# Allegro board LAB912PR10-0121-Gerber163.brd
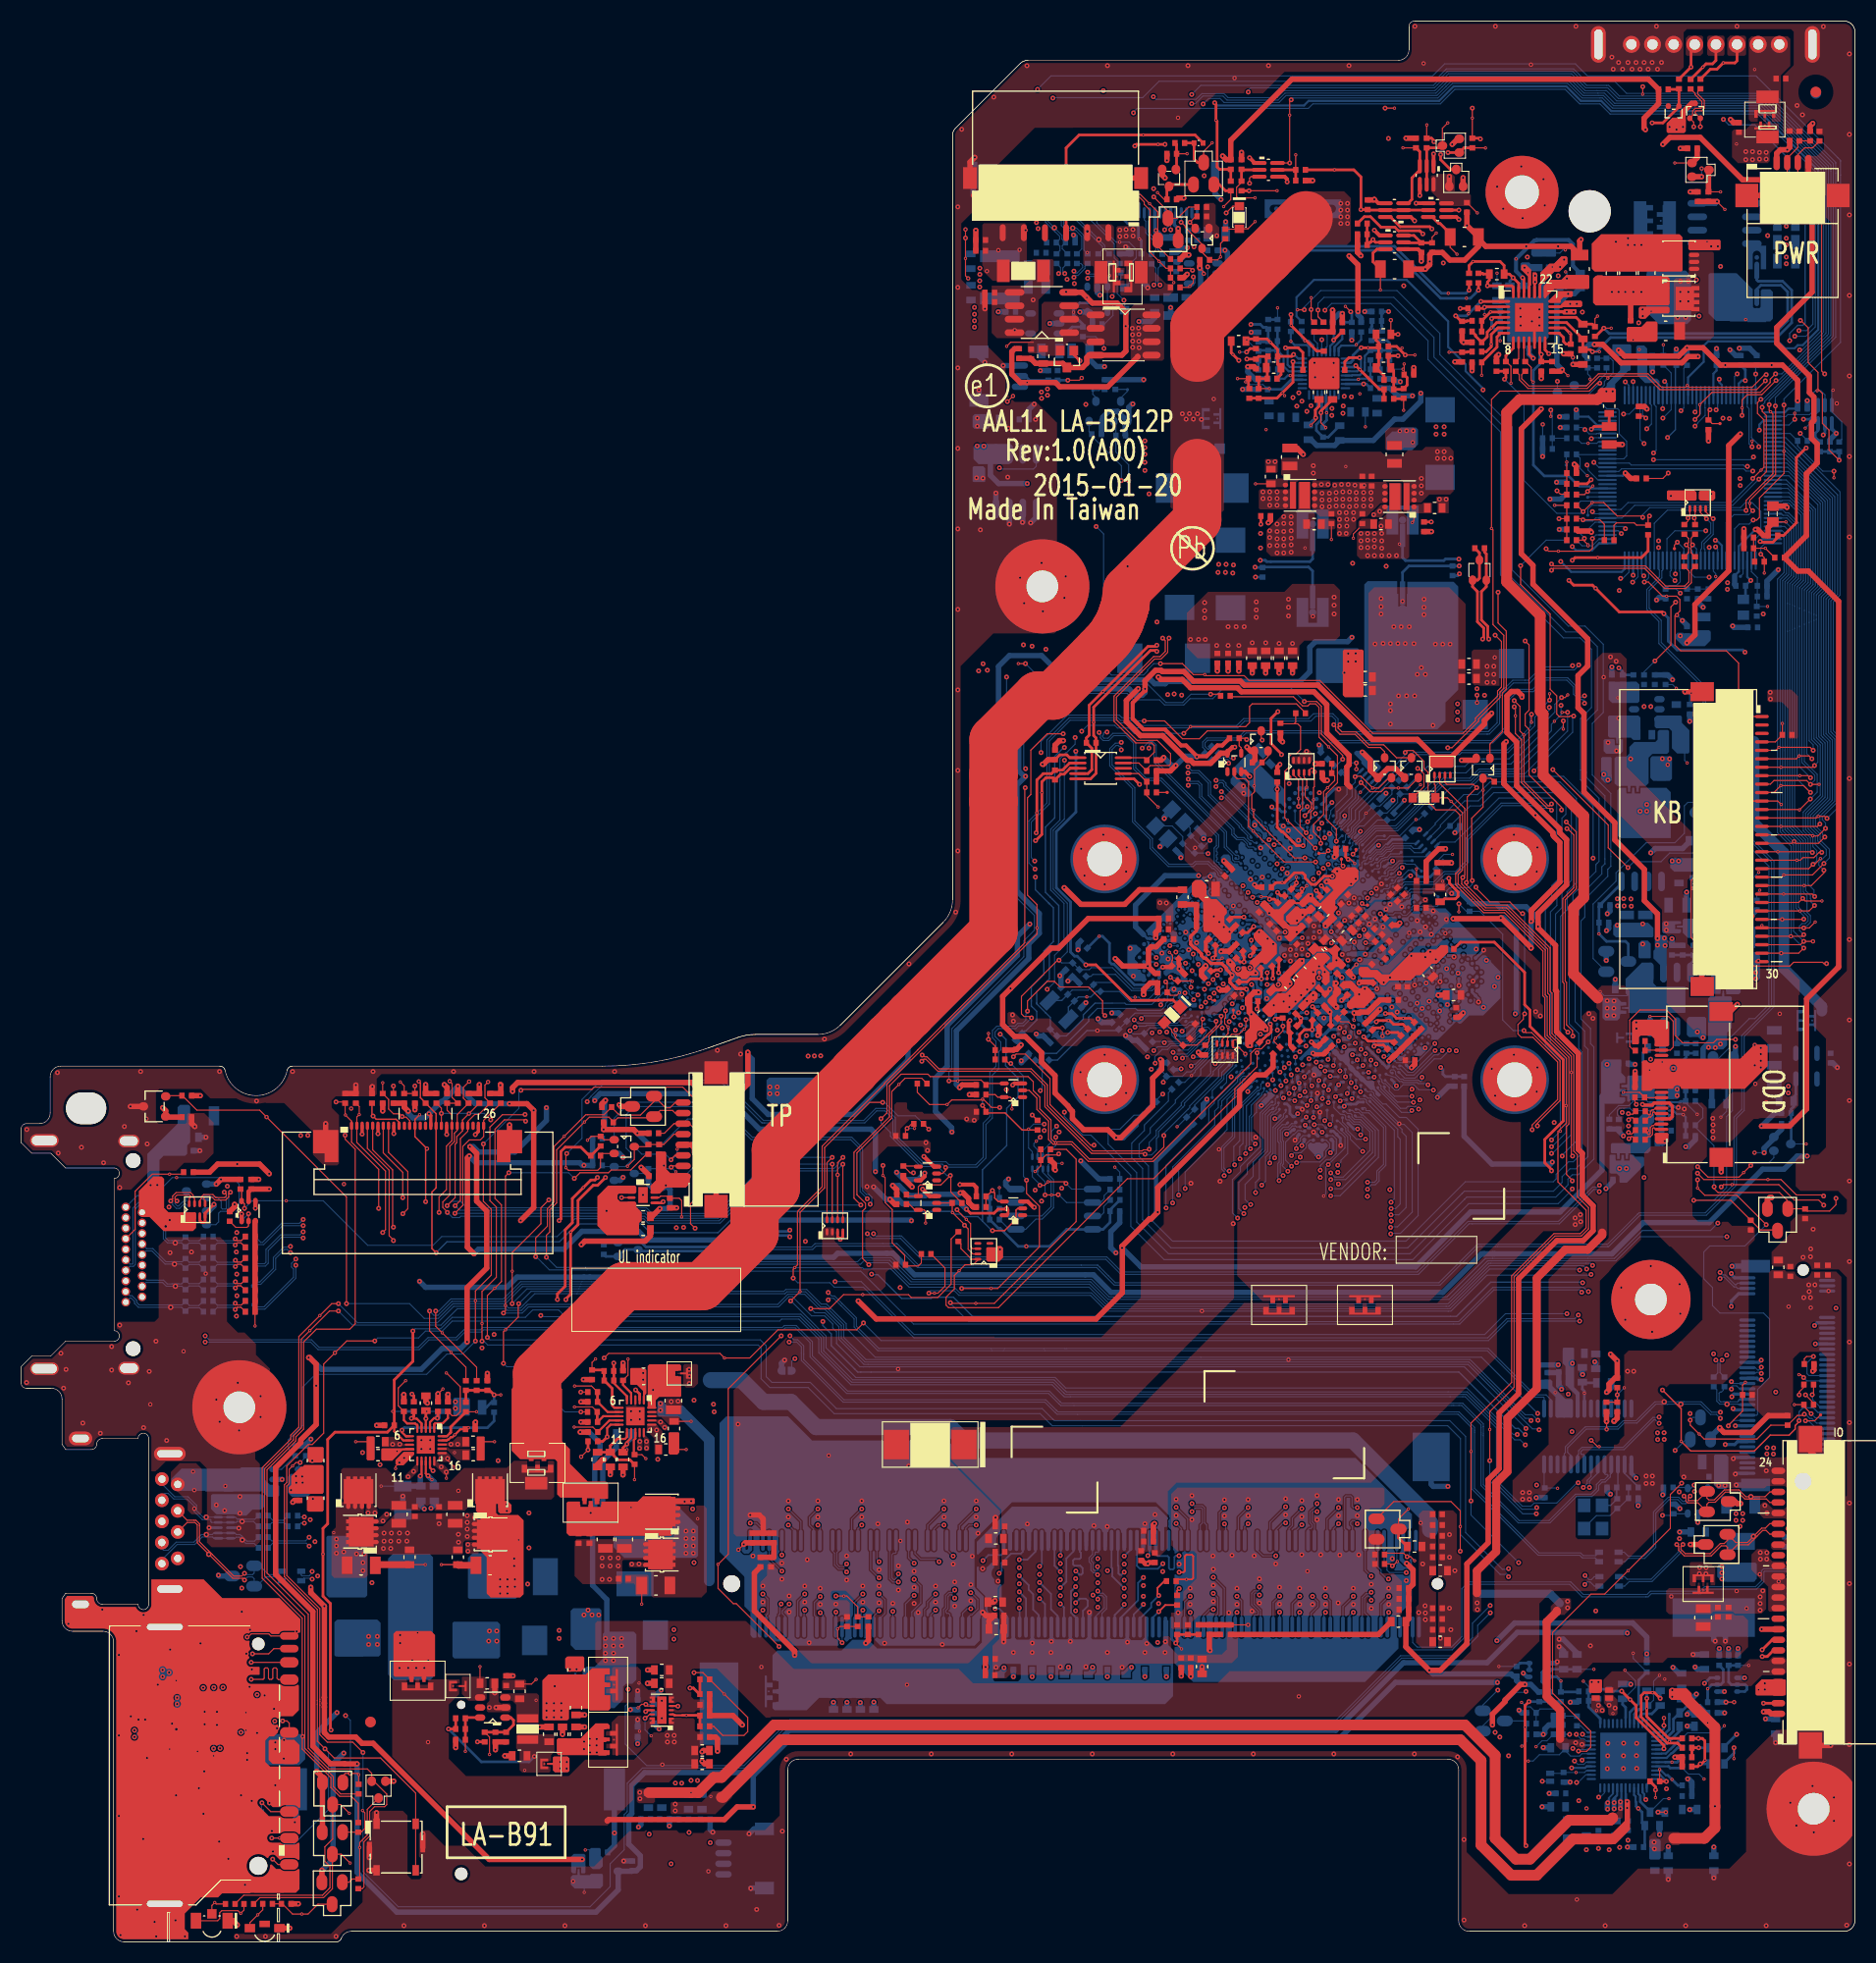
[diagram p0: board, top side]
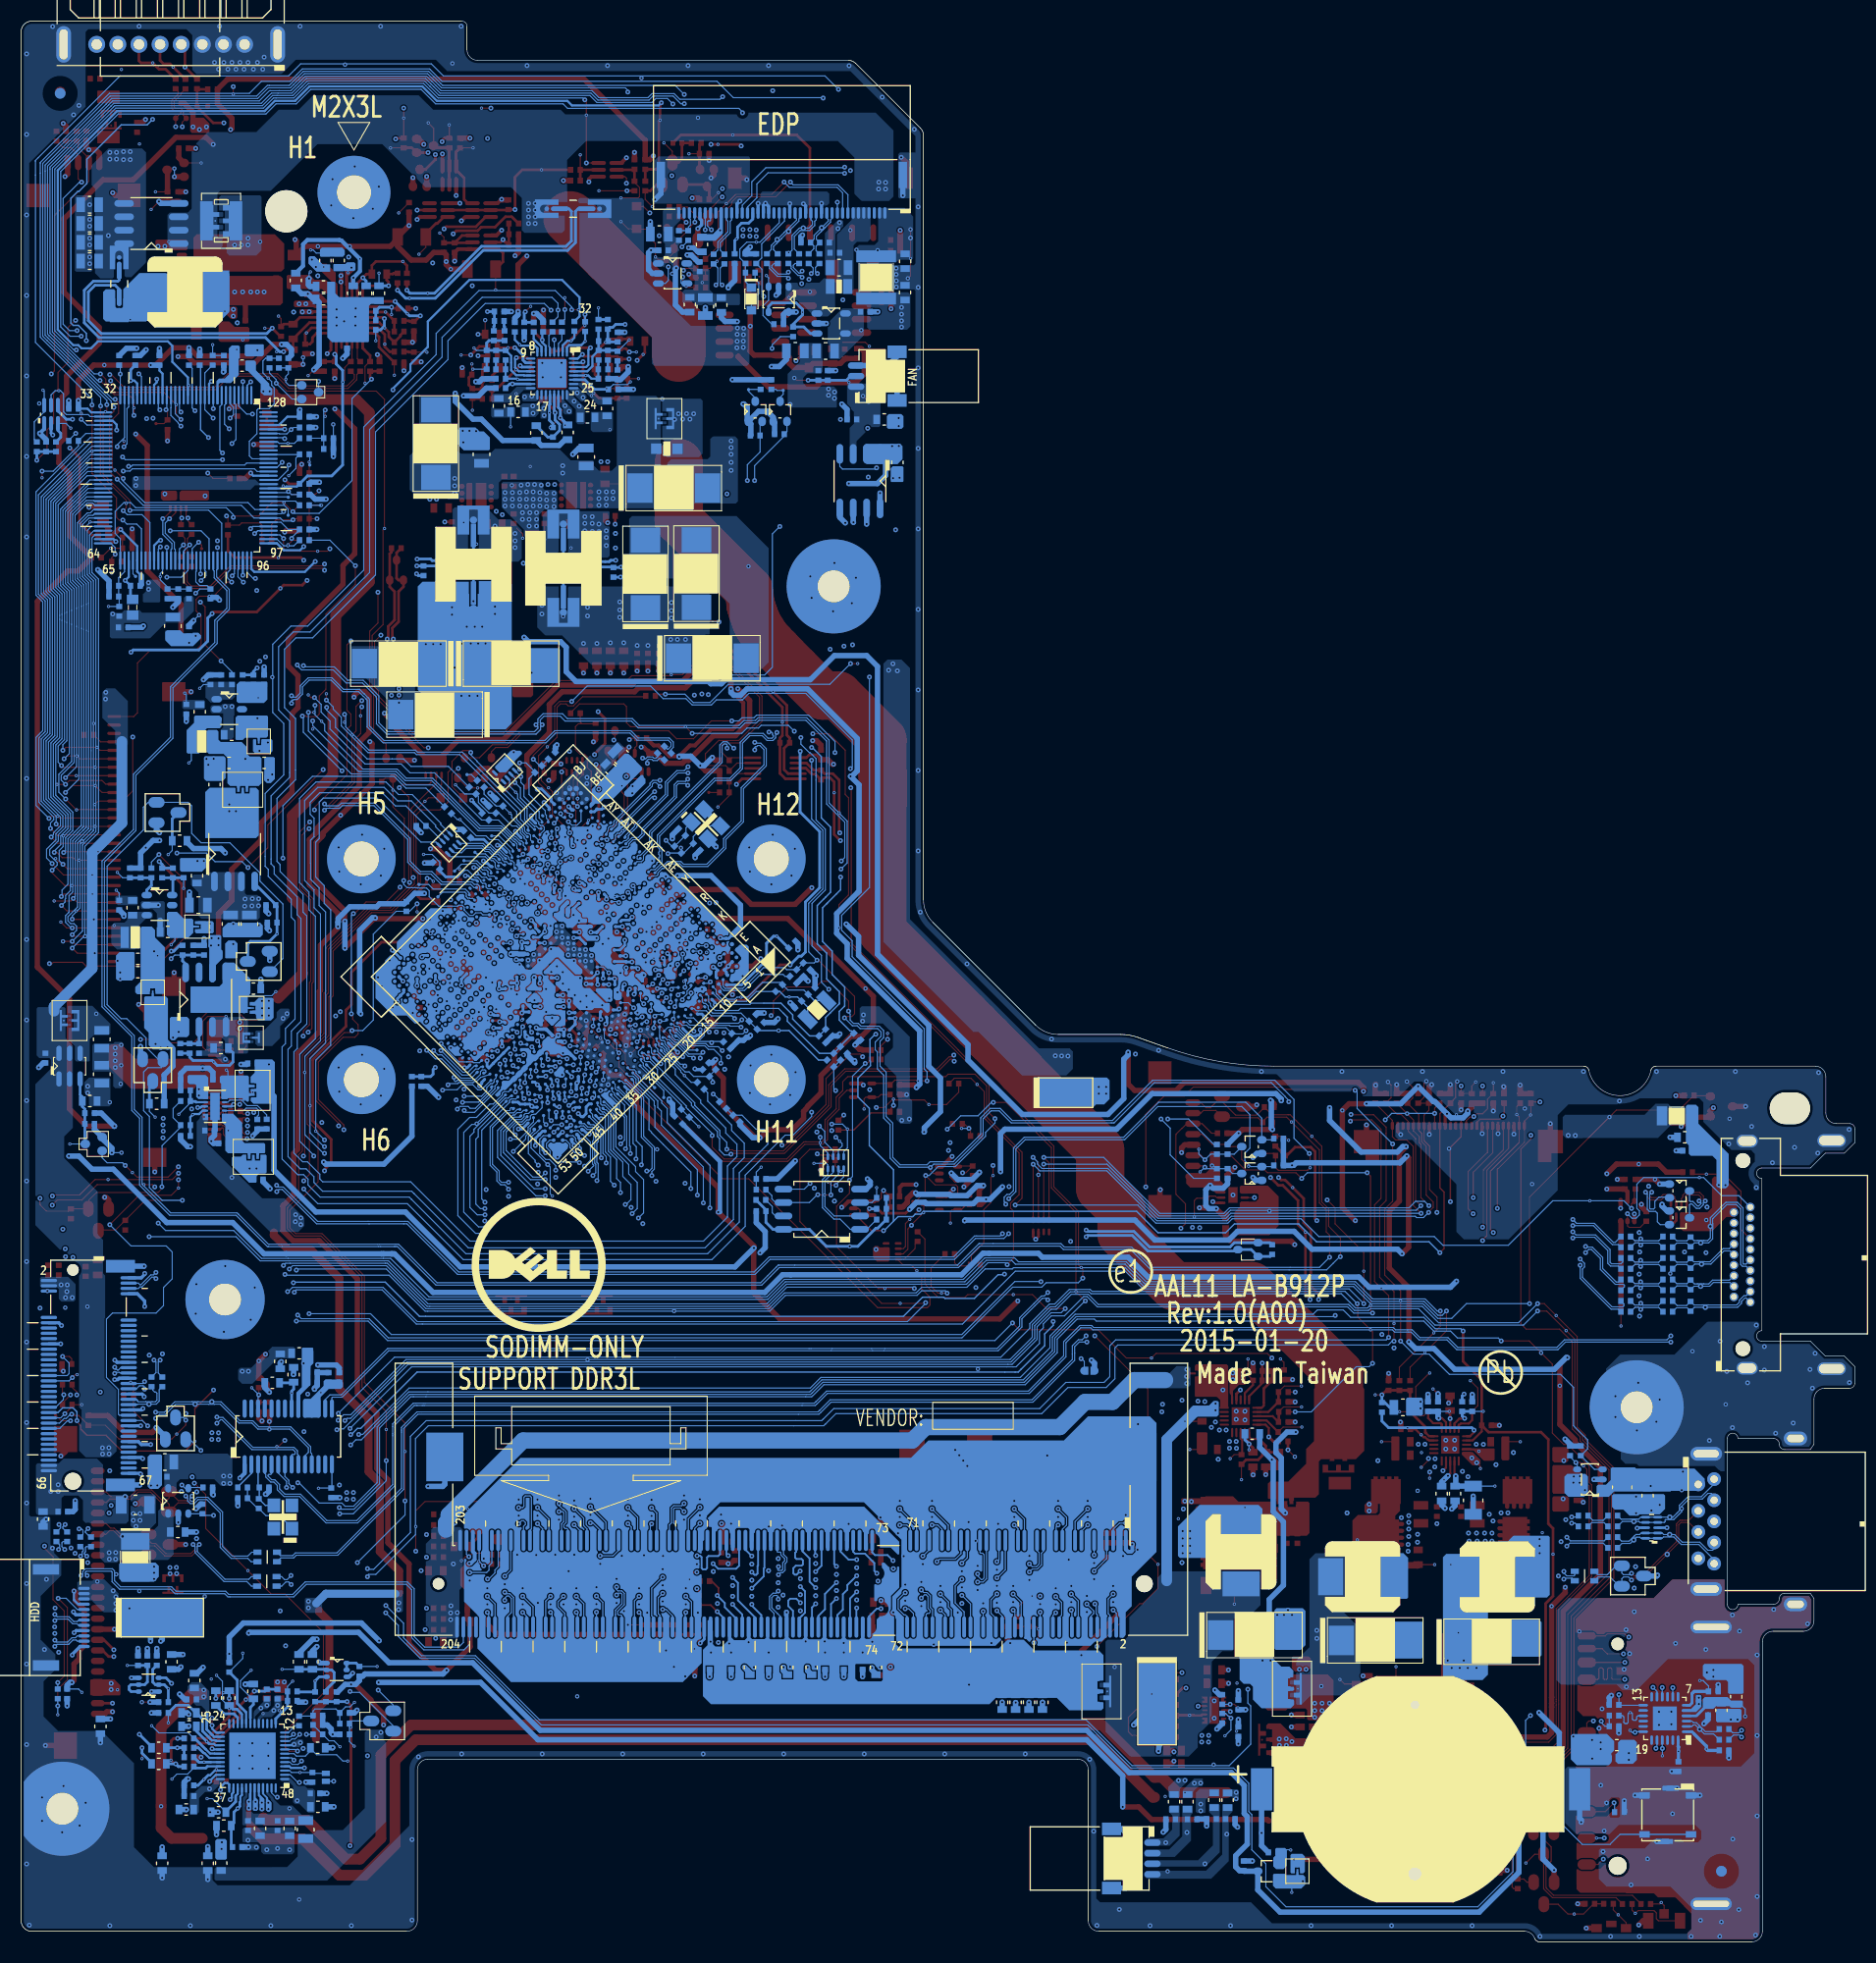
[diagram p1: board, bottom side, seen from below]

Outline 173.55 x 181.8 mm; copper layers: TOP, VCC, IN1, IN2, GND, BOTTOM. Coordinates in mm from the lower left corner of the outline.
Outline path: 0.5,52.4 arc(0.15,52.55) 0,52.9 0,54.45 1,55.45 2.8,55.45 4.2,56.85 8.8,56.85 arc(9.3,57.35) 8.8,57.85 8.8,72.25 arc(9.3,72.75) 8.8,73.25 4.2,73.25 2.8,74.65 1,74.65 0,75.65 0,76.95 arc(0.15,77.3) 0.5,77.45 1.75,77.45 arc(2.46,77.74) 2.75,78.45 2.75,81.89 arc(3.04,82.6) 3.75,82.89 18.81,82.89 ; 0.5,52.4 2.87,52.4 ; 0.5,52.4 2.87,52.4 ; 2.87,52.4 arc(3.58,52.11) 3.87,51.4 3.87,47.1 4.22,46.6 6.65,46.6 arc(7,46.75) 7.15,47.1 arc(7.31,47.49) 7.7,47.65 11.07,47.65 arc(11.57,48.15) 12.07,47.65 12.07,31.95 arc(11.57,31.45) 11.07,31.95 7.7,31.95 arc(7.31,32.11) 7.15,32.5 arc(7,32.85) 6.65,33 4.22,33 3.87,32.5 3.87,30.4 arc(4.16,29.69) 4.87,29.4 ; 18.81,82.89 arc(19.13,82.78) 19.3,82.49 ; 18.81,82.89 arc(19.13,82.78) 19.3,82.49 ; 4.87,29.4 7.75,29.4 ; 4.87,29.4 7.75,29.4 ; 7.75,29.4 arc(8.46,29.11) 8.75,28.4 8.75,1 arc(9.04,0.29) 9.75,0 ; 9.75,0 29.84,0 ; 9.75,0 29.84,0 ; 29.84,0 arc(30.12,0.09) 30.31,0.33 ; 29.84,0 arc(30.12,0.09) 30.31,0.33 ; 19.3,82.49 arc(22.24,80.1) 25.18,82.49 ; 25.18,82.49 arc(25.35,82.78) 25.67,82.89 ; 25.18,82.49 arc(25.35,82.78) 25.67,82.89 ; 25.67,82.89 55.01,82.89 arc(60.08,83.32) 65,84.6 ; 30.31,0.33 arc(30.67,0.82) 31.25,1 ; 31.25,1 71.55,1 ; 31.25,1 71.55,1 ; 71.55,1 arc(72.26,1.29) 72.55,2 ; 65,84.6 67.84,85.61 ; 65,84.6 67.84,85.61 ; 67.84,85.61 arc(68.66,85.82) 69.51,85.89 ; 67.84,85.61 arc(68.66,85.82) 69.51,85.89 ; 69.51,85.89 75.41,85.89 ; 69.51,85.89 75.41,85.89 ; 75.41,85.89 arc(76.56,86.12) 77.53,86.77 ; 72.55,16.29 72.55,2 ; 72.55,16.29 arc(72.84,17) 73.55,17.29 135.05,17.29 arc(135.76,17) 136.05,16.29 136.05,2 arc(136.34,1.29) 137.05,1 ; 72.55,16.29 72.55,2 ; 77.53,86.77 87.27,96.51 ; 77.53,86.77 87.27,96.51 ; 87.27,96.51 arc(87.92,97.48) 88.15,98.63 ; 88.15,170.98 88.15,98.63 ; 88.15,170.98 arc(88.23,171.36) 88.44,171.68 ; 88.15,170.98 arc(88.23,171.36) 88.44,171.68 ; 88.15,170.98 88.15,98.63 ; 88.44,171.68 94.56,177.8 ; 88.44,171.68 94.56,177.8 ; 94.56,177.8 arc(94.88,178.01) 95.26,178.09 ; 94.56,177.8 arc(94.88,178.01) 95.26,178.09 ; 95.26,178.09 130.35,178.09 arc(131.06,178.38) 131.35,179.09 ; 131.35,181.3 131.35,179.09 ; 131.35,181.3 arc(131.5,181.65) 131.85,181.8 ; 131.35,181.3 131.35,179.09 ; 131.85,181.8 172.55,181.8 ; 131.85,181.8 172.55,181.8 ; 172.55,181.8 arc(173.26,181.51) 173.55,180.8 ; 172.55,181.8 arc(173.26,181.51) 173.55,180.8 ; 137.05,1 172.55,1 ; 137.05,1 172.55,1 ; 172.55,1 arc(173.26,1.29) 173.55,2 ; 172.55,1 arc(173.26,1.29) 173.55,2 ; 173.55,180.8 173.55,2 ; 173.55,180.8 173.55,2

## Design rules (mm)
net group 20/15: nets USB20_JUSB2_N1_R USB20_JUSB2_P1_R
net group CSI: nets CSIN CSIP
net group DDI-COMP: nets DDI0_RCOMPN DDI0_RCOMPP
net group DIFFPAIR4: nets EC_SMB_CK2_EC EC_SMB_DA2_EC
net group DIFFPAIR7: nets MIC_CLK MIC_DATA
net group DIFFPAIR9: nets THERMAL_SMB_CK2 THERMAL_SMB_DA2
net group DIFFPAIR10: nets VCORE_GSNS VCORE_VSNS
net group PCIE-COMP: nets PCIE_RCOMPN PCIE_RCOMPP
net group REMOTE1: nets REMOTE1+ REMOTE1-
net group REMOTE2: nets REMOTE2+ REMOTE2-
net group SATA-RCOMP: nets SATA_RCOMPN SATA_RCOMPP
net group VSUM: nets VSUM+ VSUM-
net group VSUMG: nets VSUMG+ VSUMG-
net group 10: nets AUD_HP_OUT_L_CN AUD_HP_OUT_R_CN HPOUT-L HPOUT-R LINE-IN-L LINE-IN-R N17354752 N100764996 N100765116 N100768540
net group 15: nets EC_RSMRST# KB_RST# MIC_CLK_C PLT_RST# PMC_PLTRST# PMC_SUSCLK SOC_KBRST#
net group 20: nets DDR_RCOMP0 DDR_RCOMP1 DDR_RCOMP2 GPIO_RCOMP HSIC_RCOMP HUB_XIN HUB_XOUT ICLK_USB_TERMN ICLK_USB_TERMP ILB_RTC_X1 ILB_RTC_X2 LPC_RCOMP USB3_REXT0 USB_RCOMP VGFX_VSNS
net group CLK: nets DDR_TERMN0 DDR_TERMN1 ICLK_ICOMP ICLK_RCOMP XTAL_25M_IN XTAL_25M_OUT
net group DDR-CTL: nets DDR_A_CKE0 DDR_A_CKE2 DDR_A_CS0# DDR_A_CS2# DDR_A_ODT0 DDR_A_ODT2 M_ODT0 M_ODT1
net group DDRA-ADD: nets DDR_A_BS0 DDR_A_BS1 DDR_A_BS2 DDR_A_CAS# DDR_A_MA0 DDR_A_MA1 DDR_A_MA2 DDR_A_MA3 DDR_A_MA4 DDR_A_MA5 DDR_A_MA6 DDR_A_MA7 DDR_A_MA8 DDR_A_MA9 DDR_A_MA10 DDR_A_MA11 DDR_A_MA12 DDR_A_MA13 DDR_A_MA14 DDR_A_MA15 DDR_A_RAS# DDR_A_WE#
net group DDRA-D0: nets DDR_A_D0 DDR_A_D1 DDR_A_D2 DDR_A_D3 DDR_A_D4 DDR_A_D5 DDR_A_D6 DDR_A_D7 DDR_A_DM0 DDR_A_DQS0 DDR_A_DQS#0
net group DDRA-D1: nets DDR_A_D8 DDR_A_D9 DDR_A_D10 DDR_A_D11 DDR_A_D12 DDR_A_D13 DDR_A_D14 DDR_A_D15 DDR_A_DM1 DDR_A_DQS1 DDR_A_DQS#1
net group DDRA-D2: nets DDR_A_D16 DDR_A_D17 DDR_A_D18 DDR_A_D19 DDR_A_D20 DDR_A_D21 DDR_A_D22 DDR_A_D23 DDR_A_DM2 DDR_A_DQS2 DDR_A_DQS#2
net group DDRA-D3: nets DDR_A_D24 DDR_A_D25 DDR_A_D26 DDR_A_D27 DDR_A_D28 DDR_A_D29 DDR_A_D30 DDR_A_D31 DDR_A_DM3 DDR_A_DQS3 DDR_A_DQS#3
net group DDRA-D4: nets DDR_A_D32 DDR_A_D33 DDR_A_D34 DDR_A_D35 DDR_A_D36 DDR_A_D37 DDR_A_D38 DDR_A_D39 DDR_A_DM4 DDR_A_DQS4 DDR_A_DQS#4
net group DDRA-D5: nets DDR_A_D40 DDR_A_D41 DDR_A_D42 DDR_A_D43 DDR_A_D44 DDR_A_D45 DDR_A_D46 DDR_A_D47 DDR_A_DM5 DDR_A_DQS5 DDR_A_DQS#5
net group DDRA-D6: nets DDR_A_D48 DDR_A_D49 DDR_A_D50 DDR_A_D51 DDR_A_D52 DDR_A_D53 DDR_A_D54 DDR_A_D55 DDR_A_DM6 DDR_A_DQS6 DDR_A_DQS#6
net group DDRA-D7: nets DDR_A_D56 DDR_A_D57 DDR_A_D58 DDR_A_D59 DDR_A_D60 DDR_A_D61 DDR_A_D62 DDR_A_D63 DDR_A_DM7 DDR_A_DQS7 DDR_A_DQS#7
net group DDRCLK: nets DDR_A_CLK0 DDR_A_CLK0# DDR_A_CLK2 DDR_A_CLK2#
net group EDP: nets CPU_EDP_AUX#_C CPU_EDP_AUX_C CPU_EDP_N0_C CPU_EDP_N1_C CPU_EDP_P0_C CPU_EDP_P1_C EDP_CPU_AUX EDP_CPU_AUX# EDP_CPU_LANE_N0 EDP_CPU_LANE_N1 EDP_CPU_LANE_P0 EDP_CPU_LANE_P1
net group HDA: nets HDA_BIT_CLK HDA_BITCLK_AUDIO HDA_RCOMP HDA_RST# HDA_RST_AUDIO# HDA_SDIN0 HDA_SDOUT HDA_SDOUT_AUDIO HDA_SYNC HDA_SYNC_AUDIO
net group HDMI: nets HDMI_CLK+ HDMI_CLK- HDMI_TX0+ HDMI_TX0- HDMI_TX1+ HDMI_TX1- HDMI_TX2+ HDMI_TX2- TMDS_L_TX0N TMDS_L_TX0P TMDS_L_TX1N TMDS_L_TX1P TMDS_L_TX2N TMDS_L_TX2P TMDS_L_TXCN TMDS_L_TXCP TMDS_TX0N TMDS_TX0P TMDS_TX1N TMDS_TX1P TMDS_TX2N TMDS_TX2P TMDS_TXCN TMDS_TXCP
net group I2C: nets I2C1_SCL I2C1_SDA I2C2_SCL_TP I2C2_SCL_TP_R I2C2_SDA_TP I2C2_SDA_TP_R I2C5_SCL_PNL I2C5_SCL_PNL_R I2C5_SDA_PNL I2C5_SDA_PNL_R
net group KB: nets KSI0 KSI1 KSI2 KSI3 KSI4 KSI5 KSI6 KSI7 KSO0 KSO1 KSO2 KSO3 KSO4 KSO5 KSO6 KSO7 KSO8 KSO9 KSO10 KSO11 KSO12 KSO13 KSO14 KSO15 KSO16
net group LPC: nets LPC_AD0 LPC_AD1 LPC_AD2 LPC_AD3 LPC_CLK_0 LPC_CLK_1 LPC_CLK_EC LPC_CLKRUN# LPC_FRAME# SOC_SERIRQ
net group PCIE: nets CLK_PCIE_WLAN CLK_PCIE_WLAN# CLK_PCIE_WLAN#_R CLK_PCIE_WLAN_R PCIE_PRX_DTX_N1 PCIE_PRX_DTX_P1 PCIE_PTX_C_DRX_N1 PCIE_PTX_C_DRX_P1 PCIE_PTX_DRX_N1 PCIE_PTX_DRX_P1
net group RTC: nets ILB_RTC_EXTPAD RTC_RST# RTC_TEST#
net group SATA: nets SATA_PRX_DTX_N0 SATA_PRX_DTX_N0_C SATA_PRX_DTX_N1 SATA_PRX_DTX_N1_C SATA_PRX_DTX_P0 SATA_PRX_DTX_P0_C SATA_PRX_DTX_P1 SATA_PRX_DTX_P1_C SATA_PTX_DRX_N0 SATA_PTX_DRX_N0_C SATA_PTX_DRX_N1 SATA_PTX_DRX_N1_C SATA_PTX_DRX_P0 SATA_PTX_DRX_P0_C SATA_PTX_DRX_P1 SATA_PTX_DRX_P1_C
net group SD: nets MS_CLK_SD_WP MS_D1_SD_D3 MS_D2_SD_CLK MS_D2_SD_CLK_R SD_CD# SD_CMD SD_D0 SD_D1 SD_D2
net group SMBUS: nets CPU_DPB_CTRLCLK_R CPU_DPB_CTRLDAT_R DBG_UART_RXD DBG_UART_TXD EC_RX EC_SMB_CK1 EC_SMB_CK2 EC_SMB_DA1 EC_SMB_DA2 EC_TX HDMI_DDCCLK HDMI_DDCDATA PCU_SMB_CLK PCU_SMB_DATA TP_CLK TP_DATA
net group SPI: nets SOC_SPI_CLK SOC_SPI_CS0# SOC_SPI_MISO SOC_SPI_MOSI SPI_CLK SPI_CS0# SPI_HOLD# SPI_MISO SPI_MOSI SPI_WP#
net group SVID: nets VR_SVID_ALERT# VR_SVID_ALERT#_SOC VR_SVID_CLK VR_SVID_CLK_R VR_SVID_DATA VR_SVID_DATA_R VR_SVID_DATA_SOC
net group USB20: nets USB20_CAM_N2_R USB20_CAM_P2_R USB20_CPU_N3 USB20_CPU_P3 USB20_CR_N3_R USB20_CR_P3_R USB20_HUB_N1 USB20_HUB_N2 USB20_HUB_N3 USB20_HUB_N4 USB20_HUB_P1 USB20_HUB_P2 USB20_HUB_P3 USB20_HUB_P4 USB20_JUSB1_N0_R USB20_JUSB1_P0_R USB20_JUSB3_N3_R USB20_JUSB3_P3_R USB20_N0 USB20_N1 USB20_N2 USB20_P0 USB20_P1 USB20_P2
net group USB30: nets PCH_USB3_RX0_N PCH_USB3_RX0_P PCH_USB3_TX0_N PCH_USB3_TX0_N_C PCH_USB3_TX0_P PCH_USB3_TX0_P_C USB3RN2_JUSB1_R USB3RP2_JUSB1_R USB3TN2_JUSB1_R USB3TP2_JUSB1_R
nets with their own width: min track width 0.254; nets 1.0VS_GATE 3VS_ON 5VS_ON +1.0VS_R +1.5VSP +1.8VALW +1.8VS_OUT +3VALW_SOC +3VLP +3VS_SOC +BIOS_SPI +EC_VCCA +MIC2-VREFO +RTCBATT +V18R ACIN BATT_PRS BATT_TEMP CLK_SMB CS1 CS2 DAT_SMB EN_3V EN_5V EN_5V3V ENVDD_R ERP_LOT6 FAN_SPEED1 FB_3V FB_5V JACK_PLUG# JACK_SENSE# LINE1-L LINE1-R LINE1-VREFO-L LINE1-VREFO-R MIC1-L MIC_GND N17227663 N17227696 N17322935 N25654694 N25654700 N47008134 N48039107 N61580896 N61580898 N100764683 N100764685 N100764691 N100764720 N100764741 N100764791 N100764795 N100764809 N100764813 N100764860 N100764905 N100764954 N100765028 N100765040 N100765769 N100765781 NTC NTC_1 NTCG ODD_EN PS_ID PSID PSID-1 PSID-2 PSID-3 RING2 VGATE VR_HOT# VR_ON_R
nets with their own width: min track width 0.305; nets N40812716 RREF V18
nets with their own width: min track width 0.508; nets +1.0VALW +1.0VS +1.05VS +1.5VS +1.05VS_SOC +1.8VS +1.35V +1.35V_SOC +1.35VS +3V_HUB +3VALW +3VALWP +3VS +3VS_CAM +3VS_TP +5VALW +5VS +5VS_TOUCH +DDR_SOC_VREF +DIMM1_VREF_CA +DIMM1_VREF_DQ +FAN_POWER +INV_PWR_SRC +RTCVCC +SOC_VCC +SOC_VNN B+ BATT+ ECAGND GND GNDA HDMI_GND JHDD_P10 VIN VL
nets with their own width: min track width 0.635; nets SNB_3V SNB_5V
nets with their own width: min track width 0.762; nets +1.35VS_OUT DH_CHG DL_CHG LX_CHG
nets with their own width: min track width 1.016; nets +3VALW_EC +5V_HUB +5V_PVDD +VCC_3IN1 +VDISPLAY_VCC DH_1.35VP DL_1.35VP LG_3V LG_5V LGATE1 LGATEG LX_3V LX_5V PHASE1 PHASEG RING2_R SW_1.35VP UG_3V UG_5V UGATE1 UGATEG1
nets with their own width: min track width 1.524; nets +0.675VS +LCDVDD +LCDVDD_CONN
nets with their own width: min track width 2.032; nets +5V_USB_PWR1 +5V_USB_PWR2 +5VS_ODD +5VS_ODD_R1
nets with their own width: min track width 2.54; nets +3VS_WLAN_NGFF
nets with their own width: min track width 3.81; nets +3VS_OUT
nets with their own width: min track width 4.572; nets +5VS_OUT

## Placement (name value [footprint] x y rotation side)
C1  0.1U_0402_16V4Z  [C_0402]  15.22 78.06 0 top
C2  0.1U_0402_16V4Z  [C_0402]  167.38 170.49 90 top
C3  0.1U_0402_16V4Z  [C_0402]  170.2 171.37 270 top
C967  330P_0402_50V7K  [C_0402]  59.87 20.71 90 bottom
C976  330P_0402_50V7K  [C_0402]  59.87 23.4 270 bottom
C979  .1U_0402_16V7K  [C_0402]  65.16 23.45 180 top
C980  .1U_0402_16V7K  [C_0402]  64.24 21.42 0 top
C1034  1U_0402_6.3V6K  [C_0402]  109.06 94.91 180 top
C1035  1U_0402_6.3V6K  [C_0402]  107.55 90.76 90 top
C1036  1U_0402_6.3V6K  [C_0402]  116.66 92.78 315 top
C1037  1U_0402_6.3V6K  [C_0402]  115.91 91.51 225 top
C1038  0.47U_0402_6.3V6K  [C_0402]  120.73 86.69 225 top
C1039  0.01U_0402_16V7K  [C_0402]  114.98 94.4 315 top
C1040  1U_0402_6.3V6K  [C_0402]  122.71 87.93 45 top
C1041  1U_0402_6.3V6K  [C_0402]  124.53 91.68 135 top
C1042  1U_0402_6.3V6K  [C_0402]  125.66 91.79 135 top
C1043  1U_0402_6.3V6K  [C_0402]  120.08 98.28 315 top
C1044  1U_0402_6.3V6K  [C_0402]  117.3 94.69 225 top
C1045  1U_0402_6.3V6K  [C_0402]  114.81 89.55 135 top
C1046  1U_0402_6.3V6K  [C_0402]  127.21 97.09 135 top
C1047  1U_0402_6.3V6K  [C_0402]  126.57 96.46 135 top
C1048  1U_0402_6.3V6K  [C_0402]  108.59 96.86 180 top
C1049  1U_0402_6.3V6K  [C_0402]  108.59 95.84 180 top
C1050  1U_0402_6.3V6K  [C_0402]  124.28 98.88 315 top
C1051  1U_0402_6.3V6K  [C_0402]  128.83 94.06 45 top
C1052  1U_0402_6.3V6K  [C_0402]  121.46 98.42 315 top
C1053  1U_0402_6.3V6K  [C_0402]  129.09 93.05 45 top
C1054  1U_0402_6.3V6K  [C_0402]  123.42 85.45 315 top
C1055  1U_0402_6.3V6K  [C_0402]  122.78 84.82 315 top
C1056  22U_0805_6.3V6M  [C_0805]  151.95 95.5 90 bottom
C1057  22U_0805_6.3V6M  [C_0805]  153.73 95.5 90 bottom
C1058  1U_0402_6.3V6K  [C_0402]  127.84 92.53 225 top
C1059  22U_0805_6.3V6M  [C_0805]  157.63 98.13 180 bottom
C1060  1U_0402_6.3V6K  [C_0402]  111.96 91.25 45 top
C1061  1U_0402_6.3V6K  [C_0402]  126.17 90.28 225 top
C1062  1U_0402_6.3V6K  [C_0402]  117.73 93 315 top
C1063  .1U_0402_16V7K  [C_0402]  111.23 97.11 0 top
C1064  1U_0402_6.3V6K  [C_0402]  128.8 95.34 225 top
C1065  1U_0402_6.3V6K  [C_0402]  111.23 98.13 0 top
C1066  1U_0402_6.3V6K  [C_0402]  128.08 95.89 225 top
C1067  1U_0402_6.3V6K  [C_0402]  111.23 96.1 0 top
C1068  1U_0402_6.3V6K  [C_0402]  119.45 97.64 315 top
C1069  .1U_0402_16V7K  [C_0402]  124.91 99.77 315 top
C1070  0.01U_0402_16V7K  [C_0402]  128.59 91.4 225 top
C1071  1U_0402_6.3V6K  [C_0402]  130.26 98.49 135 top
C1072  1U_0402_6.3V6K  [C_0402]  130.89 99.12 135 top
C1073  1U_0402_6.3V6K  [C_0402]  132.06 97.87 0 top
C1074  1U_0402_6.3V6K  [C_0402]  114.99 93.12 135 top
C1075  1U_0402_6.3V6K  [C_0402]  134.04 101.23 90 top
C1076  .1U_0402_16V7K  [C_0402]  71.24 37.77 90 top
C1078  .1U_0402_16V7K  [C_0402]  112.45 30.01 270 top
C1117  .1U_0402_16V7K  [C_0402]  146.44 53.93 180 bottom
C1118  .1U_0402_16V7K  [C_0402]  146.44 52.92 180 bottom
C1119  10U_0603_10V6M  [C_0603]  147.76 52.98 90 bottom
C1120  10U_0603_6.3V6M  [C_0603]  149.03 55.65 270 bottom
C1121  0.01U_0402_16V7K  [C_0402]  151.06 51.09 270 top
C1122  0.01U_0402_16V7K  [C_0402]  144.46 53.88 270 bottom
C1123  330P_0402_50V7K  [C_0402]  151.2 76.93 90 bottom
C1124  .1U_0402_16V7K  [C_0402]  155.4 81.62 180 bottom
C1125  .1U_0402_16V7K  [C_0402]  158.45 80.6 180 bottom
C1126  .1U_0402_16V7K  [C_0402]  154.86 75.59 180 bottom
C1127  330P_0402_50V7K  [C_0402]  150.31 76.94 90 bottom
C1128  .1U_0402_16V7K  [C_0402]  158.45 76.28 180 bottom
C1129  4.7U_0603_6.3V6K  [C_0603]  155.25 110.26 270 bottom
C1130  4.7U_0603_6.3V6K  [C_0603]  156.9 101.62 270 bottom
C1131  .1U_0402_16V7K  [C_0402]  149.46 98.13 0 bottom
C1132  12P_0402_50V8J~N  [C_0402]  152.13 41.99 0 bottom
C1133  12P_0402_50V8J~N  [C_0402]  151.01 43.01 180 bottom
C1138  .1U_0402_16V7K  [C_0402]  58.35 19.44 90 bottom
C1139  .1U_0402_16V7K  [C_0402]  58.35 21.98 90 bottom
C1143  1U_0402_6.3V6K  [C_0402]  65.16 19.39 180 top
C1144  1U_0402_6.3V6K  [C_0402]  65.16 22.44 180 top
C1145  1U_0402_6.3V6K  [C_0402]  158.45 81.62 180 bottom
C1146  1U_0402_6.3V6K  [C_0402]  155.25 76.79 0 bottom
C1147  1U_0402_6.3V6K  [C_0402]  151.19 83.14 0 bottom
C1148  1U_0402_6.3V6K  [C_0402]  151.57 72.16 180 bottom
C2305  10U_0603_6.3V6M  [C_0603]  61.33 24.47 180 top
C2306  10U_0603_6.3V6M  [C_0603]  61.33 25.74 180 top
C2307  10U_0805_10V4Z  [C_0805]  52.51 24.89 90 top
C2308  10U_0603_6.3V6M  [C_0603]  52.51 22.88 270 top
C2316  10U_0603_6.3V6M  [C_0603]  63.75 18.12 0 top
C2318  10U_0603_6.3V6M  [C_0603]  63.75 16.85 0 top
C2323  10U_0603_6.3V6M  [C_0603]  52.51 18.94 90 top
C2324  10U_0603_6.3V6M  [C_0603]  51.24 18.94 90 top
C2498  0.1U_0402_10V6K  [C_0402]  97.85 111.89 90 top
C2500  2200P_0402_25V7K  [C_0402]  55.15 65.07 90 bottom
C2502  2200P_0402_25V7K  [C_0402]  97.85 110.9 270 top
C2504  2200P_0402_25V7K  [C_0402]  100.82 113.5 0 top
C2505  2200P_0402_25V7K  [C_0402]  137.59 131.91 0 top
CA1  10U_0603_6.3V6M  [C_0603]  147.25 25.8 90 bottom
CA2  10U_0603_6.3V6M  [C_0603]  145.98 25.8 90 bottom
CA21  22P_0402_50V8J  [C_0402]  145.93 20.53 180 bottom
CA22  22P_0402_50V8J  [C_0402]  145.98 16.04 270 bottom
CA23  2.2U_0603_6.3V6K  [C_0603]  158.36 20.4 180 bottom
CA24  1U_0402_6.3V6K  [C_0402]  154.16 15.2 0 top
CA25  1U_0402_6.3V6K  [C_0402]  158.12 14.82 180 bottom
CA29  1000P_0402_50V7K  [C_0402]  59.57 11.63 180 bottom
CA30  1000P_0402_50V7K  [C_0402]  60.43 11.63 0 bottom
CA31  1000P_0402_50V7K  [C_0402]  63.18 11.6 180 bottom
CA32  1000P_0402_50V7K  [C_0402]  64.29 11.6 0 bottom
CA51  0.1U_0402_16V7K  [C_0402]  156.95 22.94 0 bottom
CA53  4.7U_0603_6.3V6K  [C_0603]  148.14 11.45 270 bottom
CA54  0.1U_0402_16V7K  [C_0402]  152.08 11.46 270 bottom
CA55  4.7U_0603_6.3V6K  [C_0603]  150.93 11.45 270 bottom
CA56  0.1U_0402_16V7K  [C_0402]  149.28 11.46 270 bottom
CA57  4.7U_0603_6.3V6K  [C_0603]  146.17 12.78 180 bottom
CA58  0.1U_0402_16V7K  [C_0402]  146.18 14.05 180 bottom
CA59  4.7U_0603_6.3V6K  [C_0603]  157.22 12.53 0 bottom
CA60  0.1U_0402_16V7K  [C_0402]  157.21 13.8 0 bottom
CA61  10U_0603_6.3V6M  [C_0603]  153.66 11.01 0 bottom
CA62  10U_0603_6.3V6M  [C_0603]  158.36 21.67 180 bottom
CA63  10U_0603_6.3V6M  [C_0603]  155.57 12.28 180 bottom
CA64  10U_0603_6.3V6M  [C_0603]  144.77 18.37 0 bottom
CA65  0.1U_0402_16V7K  [C_0402]  147.25 20.45 90 bottom
CA67  4.7U_0603_6.3V6K  [C_0603]  155.12 22.37 90 bottom
CA68  4.7U_0603_6.3V6K  [C_0603]  153.85 22.37 90 bottom
CA69  100P_0402_50V8J  [C_0402]  145.93 21.42 180 bottom
CA71  4.7U_0603_6.3V6K  [C_0603]  157.16 24.02 90 bottom
CA74  10U_0603_6.3V6M  [C_0603]  151.57 23.01 90 bottom
CC1  .1U_0402_16V7K  [C_0402]  125.21 88.03 45 top
CC2  .1U_0402_16V7K  [C_0402]  127.89 86.31 135 top
CC5  0.1U_0402_10V7K  [C_0402]  113.31 112.51 135 bottom
CC6  0.1U_0402_10V7K  [C_0402]  112.68 111.87 135 bottom
CC7  22P_0402_50V8J  [C_0402]  135.24 105.62 0 bottom
CC8  10P_0402_50V8J  [C_0402]  109.05 82.56 225 bottom
CC9  10P_0402_25V8K  [C_0402]  110.69 104.71 45 bottom
CC10  10P_0402_25V8K  [C_0402]  109.94 103.96 225 bottom
CC11  .1U_0402_16V7K  [C_0402]  91.32 70.57 180 top
CC12  .1U_0402_16V7K  [C_0402]  123.65 111.95 135 bottom
CC13  .1U_0402_16V7K  [C_0402]  112.07 84.87 270 top
CC14  .1U_0402_16V7K  [C_0402]  98.04 85.75 225 bottom
CC15  .1U_0402_16V7K  [C_0402]  100.79 91.39 225 bottom
CC16  .1U_0402_16V7K  [C_0402]  100.16 92.02 225 bottom
CC17  15P_0402_50V8J  [C_0402]  99.06 89.68 135 bottom
CC18  15P_0402_50V8J  [C_0402]  99.68 89.05 315 bottom
CC19  .1U_0402_16V7K  [C_0402]  124.59 87.4 225 top
CC20  1U_0402_6.3V6K  [C_0402]  94.09 85.36 45 bottom
CC21  .1U_0402_16V7K  [C_0402]  103.06 69.17 0 bottom
CC22  1U_0402_6.3V6K  [C_0402]  104.65 87.14 135 bottom
CC23  .1U_0402_16V7K  [C_0402]  57.84 6.74 90 bottom
CC24  10P_0402_50V8J  [C_0402]  103.06 72.21 0 bottom
CC25  10P_0402_50V8J  [C_0402]  128.62 106.84 45 bottom
CC26  10P_0402_50V8J  [C_0402]  127.96 107.51 45 bottom
CC27  1U_0402_6.3V6K  [C_0402]  127.75 88.31 135 top
CC28  .1U_0402_16V7K  [C_0402]  128.38 88.95 135 top
CC29  2.2U_0402_6.3V6M  [C_0402]  131.91 83.44 180 top
CC30  2.2U_0402_6.3V6M  [C_0402]  130.31 91.32 270 top
CC31  2.2U_0402_6.3V6M  [C_0402]  135.82 87.51 90 top
CC32  2.2U_0402_6.3V6M  [C_0402]  131.2 91.32 270 top
CC33  10U_0603_6.3V6M  [C_0603]  136.26 89.62 180 top
CC34  10U_0603_6.3V6M  [C_0603]  133.6 91.33 135 top
CC35  10U_0603_6.3V6M  [C_0603]  117.25 110.51 45 bottom
CC36  22U_0805_6.3V6M  [C_0805]  116.12 111.54 45 bottom
CC38  22U_0805_6.3V6M  [C_0805]  113.05 99.65 180 top
CC39  1U_0402_6.3V6K  [C_0402]  121 85.26 225 top
CC40  1U_0402_6.3V6K  [C_0402]  119.04 92.95 135 top
CC41  1U_0402_6.3V6K  [C_0402]  122.2 87.23 315 top
CC42  1U_0402_6.3V6K  [C_0402]  124.53 89.9 45 top
CC43  1U_0402_6.3V6K  [C_0402]  113.92 100.88 45 top
CC44  1U_0402_6.3V6K  [C_0402]  124.09 89.05 135 top
CC45  1U_0402_6.3V6K  [C_0402]  118.18 96.33 45 top
CC46  1U_0402_6.3V6K  [C_0402]  117.16 97.47 45 top
CC47  1U_0402_6.3V6K  [C_0402]  118.81 95.69 45 top
CC49  .1U_0402_16V7K  [C_0402]  37.27 80.3 270 top
CC50  .1U_0402_16V7K  [C_0402]  30.66 79.38 90 top
CC51  .1U_0402_16V7K  [C_0402]  38.28 79.38 90 top
CC52  .1U_0402_16V7K  [C_0402]  31.68 79.38 90 top
CC53  .1U_0402_16V7K  [C_0402]  39.3 79.38 90 top
CC54  .1U_0402_16V7K  [C_0402]  33.2 79.38 90 top
CC56  .1U_0402_16V7K  [C_0402]  40.32 79.38 90 top
CC57  .1U_0402_16V7K  [C_0402]  34.22 80.3 270 top
CC59  .1U_0402_16V7K  [C_0402]  42.35 79.38 90 top
CC61  .1U_0402_16V7K  [C_0402]  43.36 79.38 90 top
CC63  .1U_0402_16V7K  [C_0402]  44.38 79.38 90 top
CC65  .1U_0402_16V7K  [C_0402]  45.4 79.38 90 top
CD1  2.2U_0402_6.3V6M  [C_0402]  69.21 37.77 90 top
CD2  0.1U_0402_10V7K  [C_0402]  70.23 37.77 90 top
CD3  0.1U_0402_10V7K  [C_0402]  78.16 29.85 90 top
CD4  0.1U_0402_10V7K  [C_0402]  92.17 25.24 180 top
CD5  0.1U_0402_10V7K  [C_0402]  106.24 38.91 0 top
CD6  0.1U_0402_10V7K  [C_0402]  97.47 26.7 270 bottom
CD7  0.1U_0402_10V7K  [C_0402]  92.18 26.78 180 top
CD8  0.1U_0402_10V7K  [C_0402]  93.1 39.33 180 top
CD9  0.1U_0402_10V7K  [C_0402]  93.91 26.7 270 bottom
CD10  0.1U_0402_10V7K  [C_0402]  108.39 26.7 270 bottom
CD11  0.1U_0402_10V7K  [C_0402]  93.01 30.88 180 top
CD12  10U_0603_6.3V6M  [C_0603]  92.89 32.15 180 top
CD13  10U_0603_6.3V6M  [C_0603]  93 29.61 180 top
CD14  10U_0603_6.3V6M  [C_0603]  111.77 26.77 270 top
CD15  330U_D2_2.5V_R6M  [C_D2]  89.24 47.07 180 top
CD16  10U_0603_6.3V6M  [C_0603]  92.64 26.69 270 bottom
CD17  10U_0603_6.3V6M  [C_0603]  101.02 26.69 270 bottom
CD18  10U_0603_6.3V6M  [C_0603]  98.74 26.69 270 bottom
CD19  10U_0603_6.3V6M  [C_0603]  92.96 38.18 180 top
CD20  10U_0603_6.3V6M  [C_0603]  104.58 26.69 270 bottom
CD21  2.2U_0402_6.3V6M  [C_0402]  110.42 29.09 90 top
CD22  0.1U_0402_10V7K  [C_0402]  109.4 29.09 90 top
CD24  1U_0402_6.3V6K  [C_0402]  133.58 37.42 0 top
CD25  1U_0402_6.3V6K  [C_0402]  133.58 36.41 0 top
CD26  1U_0402_6.3V6K  [C_0402]  133.58 31.58 0 top
CD27  1U_0402_6.3V6K  [C_0402]  133.58 38.44 0 top
CD28  10U_0603_6.3V6M  [C_0603]  133.6 28.41 0 top
CD29  10U_0603_6.3V6M  [C_0603]  133.6 35.14 0 top
CD30  2.2U_0402_6.3V6M  [C_0402]  131.32 33.49 180 top
CD31  0.1U_0402_10V7K  [C_0402]  131.32 31.45 180 top
CD32  330U_D2_2.5V_R6M  [C_D2]  130.38 120.99 180 bottom
CD33  2.2U_0402_6.3V6M  [C_0402]  102.8 26.7 270 bottom
CD34  2.2U_0402_6.3V6M  [C_0402]  106.24 37.89 0 top
CD35  2.2U_0402_6.3V6M  [C_0402]  106.36 26.7 270 bottom
CD36  2.2U_0402_6.3V6M  [C_0402]  107.3 36.83 270 top
CD37  2.2U_0402_6.3V6M  [C_0402]  93.1 35.9 180 top
CD38  10P_0402_25V8K  [C_0402]  93.1 36.91 180 top
CD39  10P_0402_25V8K  [C_0402]  109.8 26.87 270 top
CD40  10P_0402_25V8K  [C_0402]  110.7 26.87 270 top
CD41  10P_0402_25V8K  [C_0402]  106 37.02 270 top
CD42  10P_0402_25V8K  [C_0402]  95.69 26.7 270 bottom
CD43  2.2U_0402_6.3V6M  [C_0402]  133.58 30.56 0 top
CD44  10P_0402_25V8K  [C_0402]  133.58 39.45 0 top
CD45  2.2U_0402_6.3V6M  [C_0402]  133.58 40.47 0 top
CD46  10P_0402_25V8K  [C_0402]  133.58 29.55 0 top
CD47  0.1U_0402_10V7K  [C_0402]  131.32 32.47 180 top
CD62  22U_0603_6.3V6M  [C_0603]  131.06 30.31 180 top
CE1  0.1U_0402_10V7K  [C_0402]  168.13 145.12 0 bottom
CE2  0.1U_0402_10V7K  [C_0402]  164.34 124.42 180 bottom
CE5  1000P_0402_50V7K  [C_0402]  146.28 144.36 0 bottom
CE6  1000P_0402_50V7K  [C_0402]  160.46 150.15 270 bottom
CE7  0.1U_0402_10V7K  [C_0402]  163.2 128.35 180 bottom
CE8  0.1U_0402_10V7K  [C_0402]  164.32 128.35 0 bottom
CE9  100P_0402_50V8J  [C_0402]  165.33 133.12 0 top
CE10  0.1U_0402_10V7K  [C_0402]  159.7 128.05 270 bottom
CE12  0.1U_0402_10V7K  [C_0402]  154.36 150.15 270 bottom
CE16  4.7U_0805_10V4Z  [C_0805]  150.3 143.43 270 top
CE18  100P_0402_50V8J  [C_0402]  146.28 138.01 0 bottom
CE20  0.1U_0402_16V7K  [C_0402]  168.29 170.47 90 top
CE23  1000P_0402_50V7K  [C_0402]  94.47 144.1 0 bottom
CE24  2.2U_0603_6.3V6K  [C_0603]  92.58 144.1 180 bottom
CE25  2.2U_0603_6.3V6K  [C_0603]  90.61 140.74 270 bottom
CE26  0.1U_0402_10V7K  [C_0402]  153.8 138.51 180 top
CE27  0.1U_0402_10V7K  [C_0402]  153.09 144.41 90 top
CE28  0.1U_0402_10V7K  [C_0402]  147.2 143.34 180 bottom
CE29  220P_0402_50V8J  [C_0402]  162.74 149.23 90 bottom
CE31  0.1U_0402_10V7K  [C_0402]  99.52 92.66 225 bottom
CE32  0.01U_0402_16V7K  [C_0402]  97.21 147.81 90 bottom
CE34  0.1U_0402_10V7K  [C_0402]  144.91 141.31 180 bottom
CE35  220P_0402_50V8J  [C_0402]  159.7 144.05 270 top
CE36  0.047U_0402_16V4Z  [C_0402]  156.65 149.23 90 bottom
CE59  0.1U_0402_10V6K  [C_0402]  60.33 72.47 180 top
CE60  2200P_0402_25V7K  [C_0402]  61.4 70.39 270 top
CE61  1U_0402_6.3V6K  [C_0402]  157.66 124.49 270 bottom
CI1  100U_1206_6.3V M X5R  [C_1206]  22.03 44.34 270 bottom
CI2  0.1U_0402_16V7K  [C_0402]  18.34 42.96 270 bottom
CI3  0.1U_0402_10V7K  [C_0402]  25.25 39.33 0 bottom
CI4  0.1U_0402_10V7K  [C_0402]  25.25 40.34 0 bottom
CI6  4.7U_0805_10V4Z  [C_0805]  159.1 45.42 0 bottom
CI7  0.1U_0402_16V7K  [C_0402]  159.75 44.03 0 bottom
CI12  4.7U_0805_10V4Z  [C_0805]  27.87 44.7 90 top
CI13  0.1U_0402_16V7K  [C_0402]  26.96 46.02 90 bottom
CI14  0.1U_0402_16V7K  [C_0402]  26.35 42.71 270 top
CI15  0.1U_0402_16V7K  [C_0402]  25.94 46.02 90 bottom
CI17  0.1U_0402_16V7K  [C_0402]  156.39 40.52 90 bottom
CI18  47U_0805_6.3V4Z  [C_0805]  27.87 42.84 270 top
CI19  150U_B15G_6.3VM_R70M  [C_B15G]  162.74 37.91 270 bottom
CI26  0.1U_0402_16V7K  [C_0402]  156.34 43.01 180 bottom
CI40  10U_0603_6.3V6M  [C_0603]  19.61 42.95 270 bottom
CLIP1  -  [EMIST-SQ-26G_1P]  74.68 80.38 180 bottom
CLIP2  -  [EMIST_SQ-55G_1P]  66.05 22.55 270 bottom
CLIP3  -  [EMIST_SQ-55G_1P]  160.19 30.69 180 bottom
CLRP1  SHORT PADS  [SHORTPADS]  72.45 54.06 180 bottom
CM4  22U_0603_6.3V6M~D  [C_0603]  166.3 63.14 90 top
CM5  0.1U_0402_10V7K~D  [C_0402]  171 63.13 90 top
CM6  22U_0603_6.3V6M~D  [C_0603]  171.47 40.72 270 bottom
CM7  0.1U_0402_10V7K~D  [C_0402]  170.06 40.72 180 bottom
CM8  10P_0402_50V8J  [C_0402]  167.44 63 90 top
CM9  2.2U_0402_6.3V6M  [C_0402]  169.98 63.13 90 top
CR1  0.1U_0402_10V7K  [C_0402]  13.9 22.39 270 bottom
CR2  4.7U_0603_6.3V6K  [C_0603]  12.63 22.63 270 bottom
CR3  1U_0402_6.3V6K  [C_0402]  12.93 23.71 0 bottom
CR4  1U_0402_6.3V6K  [C_0402]  16.69 16.14 90 bottom
CR6  5P_0402_50V8C  [C_0402]  23.25 20.4 180 bottom
CR7  0.1U_0402_10V7K  [C_0402]  23.25 17.36 180 bottom
CR8  4.7U_0603_6.3V6K  [C_0603]  23.23 18.63 180 bottom
CR9  22P_0402_50V8J  [C_0402]  22.33 22.44 0 bottom
CR11  22P_0402_50V8J  [C_0402]  22.74 12.28 180 bottom
CS5  1000P_0402_50V7K  [C_0402]  160.58 31.66 270 top
CS6  0.1U_0402_25V6K  [C_0402]  161.6 31.66 270 top
CS7  10U_0805_10V6K  [C_0805]  159.19 31.54 270 top
CS8  0.01U_0402_16V7K  [C_0402]  153.7 75.93 180 top
CS9  0.01U_0402_16V7K  [C_0402]  153.7 76.83 180 top
CS10  1000P_0402_50V7K  [C_0402]  153.65 80.89 180 top
CS11  0.1U_0402_25V6K  [C_0402]  153.66 81.78 180 top
CS12  10U_0805_10V6K  [C_0805]  165.92 82.98 270 bottom
CS13  1U_0402_6.3V6K  [C_0402]  171.25 84.11 270 bottom
CS14  0.01U_0402_16V7K  [C_0402]  153.71 77.73 180 top
CS15  0.01U_0402_16V7K  [C_0402]  153.71 78.62 180 top
CS16  0.1U_0603_25V7K  [C_0603]  167.76 79.59 180 bottom
CS17  0.1U_0402_25V6K  [C_0402]  153.69 85.26 180 top
CS30  0.01U_0402_16V7K  [C_0402]  170.21 38.81 270 bottom
CS31  0.01U_0402_16V7K  [C_0402]  166.93 38.32 270 bottom
CS32  0.01U_0402_16V7K  [C_0402]  169.2 38.81 270 bottom
CS34  0.01U_0402_16V7K  [C_0402]  167.95 38.32 270 bottom
CX5  0.1U_0603_25V7K  [C_0603]  89.88 159.77 270 bottom
CX6  0.1U_0402_16V7K  [C_0402]  109.33 158.1 90 bottom
CX7  4.7U_0805_10V4Z  [C_0805]  99.42 150.59 0 bottom
CX8  10U_0805_10V6K  [C_0805]  95.29 158.47 0 bottom
CX9  0.1U_0402_10V7K  [C_0402]  94.11 154.29 180 bottom
CX10  0.1U_0603_25V7K  [C_0603]  89.9 155.41 90 bottom
CX11  0.1U_0402_10V7K  [C_0402]  96.08 159.88 0 bottom
CX12  0.1U_0402_10V7K  [C_0402]  21.22 64.73 0 bottom
CX13  0.1U_0402_10V7K  [C_0402]  21.22 63.71 0 bottom
CX14  0.1U_0402_10V7K  [C_0402]  21.22 66.76 0 bottom
CX15  0.1U_0402_10V7K  [C_0402]  21.22 65.74 0 bottom
CX16  0.1U_0402_10V7K  [C_0402]  21.22 62.69 0 bottom
CX17  0.1U_0402_10V7K  [C_0402]  21.22 61.68 0 bottom
CX18  0.1U_0402_10V7K  [C_0402]  21.22 60.66 0 bottom
CX19  0.1U_0402_10V7K  [C_0402]  21.22 59.65 0 bottom
CX21  0.1U_0402_16V7K  [C_0402]  15.38 74.89 0 bottom
CX22  10U_0603_6.3V6M  [C_0603]  15.39 76.16 0 bottom
CX42  0.1U_0402_10V7K  [C_0402]  100.93 158.86 90 bottom
CX43  0.1U_0402_10V7K  [C_0402]  99.02 158.86 90 bottom
CX44  0.1U_0402_10V7K  [C_0402]  98 158.86 90 bottom
CX45  0.1U_0402_10V7K  [C_0402]  102.96 158.86 90 bottom
CX46  0.1U_0402_10V7K  [C_0402]  99.92 158.86 90 bottom
CX47  0.1U_0402_10V7K  [C_0402]  101.95 158.86 90 bottom
CX49  4.7U_0805_10V4Z  [C_0805]  112.3 161.64 0 bottom
CX50  0.1U_0402_10V7K  [C_0402]  112.3 160.1 0 bottom
CX51  4.7U_0805_10V4Z  [C_0805]  108.79 155.63 270 bottom
CX52  0.1U_0402_10V7K  [C_0402]  109.68 156.6 180 top
D25  AZC199-02S  [YSLC05CH_SOT23-3]  161.63 41.68 90 top
D26  AZC199-02S  [YSLC05CH_SOT23-3]  159.42 37.61 270 top
D27  AZC199-02S  [YSLC05CH_SOT23-3]  19.97 34.63 90 bottom
D2401  -  [RB751V-40_SOD323-2]  115.3 164.29 270 top
DA8  -  [BAT54C-7-F_SOT23-3]  140.42 20.91 270 bottom
DC1  -  [DB2J31400L_SOD323-2]  109.67 88.49 225 top
DC3  -  [LBAV70WT1G_SC70-3]  56.51 6.69 90 bottom
DE3  PESD5V0U2BT_SOT23-3~D  [PESD5V0U2BT_SOT23-3]  57.82 79.08 270 top
DI1  IP4292CZ10-TBR_XSON10_2.5X1~D  [IP4292CZ10-TBR_XSON10_2P5X1]  18.68 38.2 90 bottom
DX1  -  [RB751V-40_SOD323-2]  104.44 156.58 270 bottom
DX2  -  [RB751V-40_SOD323-2]  133.84 108.29 180 top
EC6104  SCD1U16V2KX-3GP  [C_0402]  24.63 3.6 0 top
FD1  FIDUCAL  [FIDUCIAL_C40M80]  12.63 6.69 180 bottom
FD2  FIDUCIAL  [FIDUCIAL_C40M80]  33.06 20.81 0 top
FD3  FIDUCAL  [FIDUCIAL_C40M80]  169.86 175.09 0 top
FD4  FIDUCIAL  [FIDUCIAL_C40M80]  169.86 174.96 180 bottom
FX1  1.5A_6V_1206L150PR~D  [F_1206L150PR]  15.45 78.19 0 bottom
FX2  1.5A_24V_MINISMDC150F/24~D  [F_MINISMDC150F-24]  92.63 159.55 180 bottom
H1  -  [H_3P2]  142.05 165.6 0 top
H2  -  [H_4P0N]  148.45 163.8 0 top
H3  -  [H_3P0]  20.65 50.6 0 top
H4  -  [H_3P0]  154.25 60.8 0 top
H5  -  [H_3P3]  141.35 102.5 0 top
H6  -  [H_3P3]  141.35 81.6 0 top
H7  H_3P0x3P8N  [H_3P0X3P8N]  6.15 78.9 90 top
H9  -  [H_3P0]  96.65 128.3 0 top
H10  -  [H_3P0]  169.65 12.6 0 top
H11  -  [H_3P3]  102.55 81.6 0 top
H12  -  [H_3P3]  102.55 102.5 0 top
JDB1  MOLEX_52435-2671_26P_P0.5  [MOLEX_52435-2671_26P-T]  31.27 77.25 0 top
JDIMM2  AS0A621-J4RB-7H  [FOX_AS0A621-J4RB-7H_204P-T]  69 38 180 bottom
JEDP  ACES_51540-04001-P01  [ACES_51540-04001-P01_40P-T]  91.8 163.64 0 bottom
JFAN  ACES 50224-0030N-001  [ACES_50224-0030N-001_3P-T]  94.52 147.2 90 bottom
JHDD  ACES_51625-01201-001  [ACES_51625-01201-001_12P-T]  167.6 33.46 270 bottom
JHDMI1  C-K_96067-3K28-192-124  [C-K_96067-3K28-192-124_19P-T]  9.9 60.55 90 bottom
JIO1  ACES_51524-0240N-001  [ACES_51524-0240N-001_24P]  166.3 21.59 90 top
JKB  ACES_51510-0304N-P01  [ACES_51510-0304N-P01_30P]  164.75 115.98 270 top
JNGFF  LCN_DAN05-67406-0100  [DAN05-67406-0100_67P-T]  163.37 62.85 270 bottom
JODD1  AECS_51519-02001-001  [ACES_51519-02001-001_20P-T]  155.25 76.4 90 top
JP7  -  [JUMP_43X79]  169.52 87.21 180 bottom
JP12  -  [JUMP_43X39]  52.76 7.15 270 bottom
JP13  -  [JUMP_43X79]  159.19 33.32 90 top
JP14  JUMP  [JUMP_43X118]  127.18 60.83 270 top
JP15  JUMP  [JUMP_43X118]  119.06 60.83 270 top
JP36  JUMP  [JUMP_43X118]  56.11 19.13 180 top
JP37  JUMP  [JUMP_43X118]  56.11 24.34 180 top
JP38  JUMP  [JUMP_43X79]  152.19 80.6 180 bottom
JP39  JUMP  [JUMP_43X79]  151.57 74.85 270 bottom
JPWR  JXT_FP202DH-004M10M  [JXT_FP202DH-004M10M_4P]  166.15 168.42 0 top
JREAD  TAI_PSDATE-11GLBS1NN4H0  [TAI_PSDATG-11GLBS1NN4H0_11P-T]  25.38 9.82 270 top
JRTC  LOTES_AAA-BAT-054-K01  [LOTES_AAA-BAT-054-K01_2P]  56.15 14.44 0 bottom
JSPK  ACES_50224-0040N-001  [ACES_50224-0040N-001_4P-T]  66.47 9.39 270 bottom
JTP  JXT_FP202DH-008M10M  [JXT_FP202DH-008M10M_8P]  62.65 72.44 90 top
JUSB1  PUBAUN-09FLBS1NN4H0  [TAITW_PUBAUN-09FLBS1NN4H0_9P-T]  14.82 43.3 90 bottom
LA1  BLM15BB221SN1D_2P  [MURAT_BLM15BB221SN1D_2P]  144.71 15.95 270 bottom
LA3  0_0603_5%  [R0603_0OHM]  64.43 12.56 90 bottom
LA4  0_0603_5%  [R0603_0OHM]  63.16 12.56 90 bottom
LA5  0_0603_5%  [R0603_0OHM]  60.64 12.71 90 bottom
LA6  0_0603_5%  [R0603_0OHM]  59.37 12.71 90 bottom
LA7  BLM15PX330SN1D 0402  [MURAT_BLM15BD601SN1D_2P]  150.3 23.83 270 top
LA8  0_0603_5%  [R_0603]  159.81 18.37 0 bottom
LA9  0_0603_5%  [R_0603]  159.81 16.85 0 bottom
LA10  BLM15PX330SN1D 0402  [MURAT_BLM15BD601SN1D_2P]  149.03 23.83 270 top
LE1  FBMA-L11-160808-800LMT_0603  [KC_FBMA-L11-160808-800LMT_2P]  163 125.57 90 bottom
LE2  FBMA-L11-160808-800LMT_0603  [KC_FBMA-L11-160808-800LMT_2P]  165.79 135.9 270 top
LED1  12-22A/Y2T7D-C30/2C YELLOW/WHITE  [LED_12-22A-S2ST3D-C30-2C_3P]  16.55 2 180 top
LED2  LED-W-27-GP-U  [LED_12-21C-T3D-CM2P1B18X-2C_3P]  24.45 1.3 0 top
LI2  HCM2012GA900AE_4P  [INPAQ_HCM2012GA900AE_4P]  26.51 35.08 180 bottom
LI5  HCM2012GA900AE_4P  [INPAQ_HCM2012GA900AE_4P]  149.33 35.98 0 bottom
LI6  HCM2012GA900AE_4P  [INPAQ_HCM2012GA900AE_4P]  149.37 33.67 0 bottom
LX1  FBMA-L11-201209-221LMA30T_0805  [KC_FBMA-L11-201209-221LMA30_2P]  96.97 156.69 180 bottom
NOREF  -  []  52.1 63.76 0 top
NOREF#2  -  []  3.23 216.24 0 top
NOREF#3  -  []  102.55 81.6 0 top
NOREF#4  -  []  169.65 12.6 0 top
NOREF#5  -  []  24.57 -35.22 0 top
NOREF#6  -  []  20.65 50.6 0 top
NOREF#7  -  []  96.65 128.3 0 top
NOREF#8  -  []  141.35 81.6 0 top
NOREF#9  -  []  41.33 9.23 0 top
NOREF#10  -  []  141.35 102.5 0 top
NOREF#11  -  []  154.25 60.8 0 top
NOREF#12  -  []  142.05 165.6 0 top
NOREF#13  -  []  102.55 102.5 0 top
NOREF#14  -  []  122.78 64.61 0 top
NOREF#15  -  []  91.56 139.91 0 top
NOREF#16  -  []  94.65 48.9 180 bottom
NOREF#17  -  []  61.84 64.6 180 bottom
NOREF#18  -  []  124.57 64.08 180 bottom
PBATT1  SUYIN_200277GR008M270ZR  [SUYIN_200277GR008M270ZR_8P-T]  152.4 179.6 0 bottom
PC1  1000P_0402_50V7K  [C_0402]  91.27 161.08 180 top
PC2  100P_0402_50V8J  [C_0402]  91.27 160.07 180 top
PC3  1000P_0402_50V7K  [C_0402]  92.13 155.21 180 top
PC4  100P_0402_50V8J  [C_0402]  92.13 156.1 180 top
PC5  0.01U_0402_25V7K  [C_0402]  162.58 171.28 90 top
PC6  1000P_0402_50V7K  [C_0402]  166.1 176.36 0 top
PC7  1000P_0402_50V7K  [C_0402]  146.28 139.02 0 top
PC8  0.1U_0402_25V6  [C_0402]  127.39 160.61 180 top
PC9  0.01U_0402_25V7K  [C_0402]  115.5 167.77 90 top
PC10  0.1U_0402_25V6  [C_0402]  163.96 132.93 180 top
PC11  .1U_0402_16V7K  [C_0402]  121.55 167.72 180 top
PC12  0.01U_0402_25V7K  [C_0402]  171.19 141.05 90 bottom
PC102  150U_D2_6.3VY_R15M  [C_D2]  37.57 28.41 180 bottom
PC103  150U_D2_6.3VY_R15M  [C_D2]  48.6 28.53 180 bottom
PC105  1U_0603_10V6K  [C_0603]  38.31 50.29 90 top
PC106  100P_0402_50V8J  [C_0402]  37.17 51.13 270 bottom
PC107  100P_0402_50V8J  [C_0402]  39.45 50.21 90 bottom
PC108  10U 25V K X5R 0805  [C_0805]  41.08 41.32 270 top
PC109  0.1U_0402_25V6  [C_0402]  39.55 41.18 270 top
PC110  2200P_0402_50V7K  [C_0402]  37.27 41.18 270 top
PC111  10U 25V K X5R 0805  [C_0805]  35.74 41.32 270 top
PC112  0.1U_0603_25V7K  [C_0603]  34.46 47.34 180 top
PC113  0.1U_0603_25V7K  [C_0603]  43.48 47.34 180 top
PC114  680P_0603_50V8J  [C_0603]  36.76 35.71 90 top
PC115  680P_0603_50V8J  [C_0603]  41.33 35.71 90 top
PC116  1U_0603_25V6K  [C_0603]  37.84 43.14 270 bottom
PC117  1U_0603_10V6K  [C_0603]  39.11 43.14 270 bottom
PC118  4.7U_0805_25V6-K  [C_0805]  43.63 50.59 180 bottom
PC201  220U_D2_2VY_R15M  [C_D2]  60.03 29.04 180 bottom
PC203  0.1U_0402_25V6  [C_0402]  53.78 38.64 270 top
PC204  2200P_0402_50V7K  [C_0402]  52.76 38.64 270 top
PC205  10U 25V K X5R 0805  [C_0805]  57.08 38.95 270 top
PC206  10U 25V K X5R 0805  [C_0805]  55.3 38.95 270 top
PC207  0.1U_0603_25V7K  [C_0603]  61.73 46.6 180 top
PC208  10U_0805_6.3V6K  [C_0805]  61.73 52.07 270 top
PC209  10U_0805_6.3V6K  [C_0805]  59.76 53.53 180 top
PC210  1U_0603_10V6K  [C_0603]  56.97 44.95 90 top
PC211  680P_0402_50V7K  [C_0402]  57.46 34.37 180 top
PC212  0.033U_0402_16V7K  [C_0402]  56.97 53.14 90 top
PC213  1U_0603_10V6K  [C_0603]  55.76 46.35 270 top
PC214  0.1U_0402_10V7K  [C_0402]  54.55 49.21 180 top
PC215  0.1U_0402_10V7K  [C_0402]  54.55 51.11 180 top
PC216  220P_0402_25V8J  [C_0402]  55.17 54.03 0 top
PC300  22U_0603_6.3V6M  [C_0603]  160.39 95.59 180 bottom
PC301  68P_0402_50V8J  [C_0402]  160.2 101.63 270 bottom
PC302  22U_0603_6.3V6M  [C_0603]  161.79 91.78 0 bottom
PC303  22U_0603_6.3V6M  [C_0603]  161.79 93.05 0 bottom
PC304  .1U_0402_16V7K  [C_0402]  163.25 100.72 90 bottom
PC305  680P_0402_50V7K  [C_0402]  164.27 98.59 270 bottom
PC306  680P_0402_50V7K  [C_0402]  157.92 117.13 270 bottom
PC307  22U_0603_6.3V6M  [C_0603]  154.34 114.26 180 bottom
PC308  22U_0603_6.3V6M  [C_0603]  151.25 111.59 180 bottom
PC309  .1U_0402_16V7K  [C_0402]  155.63 119.01 90 bottom
PC310  68P_0402_50V8J  [C_0402]  152.58 119.92 270 bottom
PC311  22U_0603_6.3V6M  [C_0603]  153.16 111.59 0 bottom
PC400  22U_0603_6.3V6M  [C_0603]  44.82 24.47 180 top
PC401  68P_0402_50V8J  [C_0402]  41.13 21.17 0 top
PC402  22U_0603_6.3V6M  [C_0603]  47.87 17.61 180 top
PC403  22U_0603_6.3V6M  [C_0603]  49.97 18.94 90 top
PC404  .1U_0402_16V7K  [C_0402]  45.9 19.85 270 top
PC405  680P_0402_50V7K  [C_0402]  45.9 24.26 90 top
PC411  1U_0402_6.3V6K  [C_0402]  154.77 93.45 180 bottom
PC412  4.7U_0603_6.3V6K  [C_0603]  152.27 90.23 180 bottom
PC413  0.01U_0402_25V7K  [C_0402]  157.6 84.11 90 bottom
PC414  22U_0603_6.3V6M  [C_0603]  153.94 84.6 0 bottom
PC415  .1U_0402_16V7K  [C_0402]  157.26 93.4 90 bottom
PC501  33U_D2_25VM_R40M  [C_D2]  114.98 137.6 180 bottom
PC502  1000P_0402_50V7K  [C_0402]  117.09 151.44 90 bottom
PC503  0.01UF_0402_25V7K  [C_0402]  122.23 148.78 180 top
PC504  120P_0402_50V8J  [C_0402]  118.9 149.72 90 bottom
PC505  470P_0402_50V7K  [C_0402]  118.91 152.64 90 bottom
PC506  6800P_0402_25V7K  [C_0402]  116.24 147.02 270 top
PC507  1000P_0402_50V8-J  [C_0402]  118.02 149.72 90 bottom
PC508  2200P_0402_50V7K  [C_0402]  126.93 138.72 270 top
PC509  10U 25V K X5R 0805  [C_0805]  129.98 139.95 90 top
PC510  10U 25V K X5R 0805  [C_0805]  120.07 139.7 90 bottom
PC511  820PF_0402_50V7K  [C_0402]  117.11 148.78 270 bottom
PC512  .1U_0402_16V7K  [C_0402]  116.87 149.82 270 top
PC513  0.1U_0603_25V7K  [C_0603]  117.84 149 0 top
PC514  0.033U 25V K X7R 0402  [C_0402]  117.94 147.96 0 top
PC515  0.1U_0603_25V7K  [C_0603]  119.24 144.29 0 bottom
PC516  680P_0402_50V7K  [C_0402]  124.01 134.25 90 top
PC517  1U_0603_10V6K  [C_0603]  122.84 147.39 270 top
PC518  1U_0603_10V6K  [C_0603]  124.11 145.99 90 top
PC519  10U 25V K X5R 0805  [C_0805]  120.07 139.7 90 top
PC520  47P_0402_50V8J  [C_0402]  124.15 152.39 90 bottom
PC521  0.1U_0402_25V6  [C_0402]  127.82 138.72 270 top
PC522  10U 25V K X5R 0805  [C_0805]  129.98 139.95 90 bottom
PC523  0.1U_0402_16V7K  [C_0402]  124.13 153.3 0 top
PC524  0.1U_0603_25V7K  [C_0603]  127.22 144.81 180 bottom
PC525  820PF_0402_50V7K  [C_0402]  129.49 147.94 90 bottom
PC526  680P_0402_50V7K  [C_0402]  126.93 134.25 90 top
PC527  470P_0402_50V7K  [C_0402]  128.76 153.42 180 bottom
PC528  180P_0402_50V8J  [C_0402]  127.69 150.64 270 bottom
PC529  0.033U 25V K X7R 0402  [C_0402]  128.99 147.84 0 top
PC530  0.1U_0603_25V7K  [C_0603]  128.24 148.98 0 top
PC531  1000P_0402_50V8-J  [C_0402]  128.61 148.85 180 bottom
PC532  6800P_0402_25V7K  [C_0402]  130.84 146.11 90 top
PC533  330P_0402_50V7K  [C_0402]  127.84 154.31 0 bottom
PC534  .1U_0402_16V7K  [C_0402]  130.89 148.34 0 top
PC535  0.01UF_0402_25V7K  [C_0402]  124.36 148.78 0 top
PC536  33U_D2_25VM_R40M  [C_D2]  134.3 138.62 90 bottom
PC700  0.1U_0603_25V7K  [C_0603]  96.74 150.8 270 top
PC701  5600P_0402_25V7K  [C_0402]  94.44 149.88 90 top
PC702  10U_0805_25V6K  [C_0805]  152.08 158.8 270 top
PC703  10U_0805_25V6K  [C_0805]  153.85 158.8 270 top
PC704  2200P_0402_25V7K  [C_0402]  149.41 158.4 270 top
PC705  0.1U_0603_25V7K  [C_0603]  150.55 158.64 270 top
PC706  0.1U_0603_25V7K  [C_0603]  139.68 156.75 270 bottom
PC707  0.1U_0603_25V7K  [C_0603]  140.9 156.75 270 bottom
PC708  0.1U_0402_10V7K  [C_0402]  127.44 163.96 90 top
PC709  0.047U_0603_25V7M  [C_0603]  138.96 157.86 0 top
PC710  1U_0603_10V6K  [C_0603]  142.12 156.75 270 bottom
PC711  1U_0603_25V6K  [C_0603]  145.64 156.69 180 bottom
PC712  0.01U_0402_50V7K  [C_0402]  140.9 154.38 180 bottom
PC713  0.1U_0603_25V7K  [C_0603]  144.76 159.85 270 bottom
PC714  1U_0603_10V6K  [C_0603]  145.64 155.47 180 bottom
PC715  0.1U_0402_10V7K  [C_0402]  142.7 150.85 90 bottom
PC716  680P_0402_50V7K  [C_0402]  152.33 152.53 90 top
PC717  10U 25V K X5R 0805  [C_0805]  166.21 164.42 0 bottom
PC718  10U 25V K X5R 0805  [C_0805]  166.21 159.09 0 bottom
PC719  10U 25V K X5R 0805  [C_0805]  166.21 160.87 0 bottom
PC720  10U 25V K X5R 0805  [C_0805]  166.21 162.64 0 bottom
PC721  2200P_0402_25V7K  [C_0402]  139.99 152.57 0 bottom
PC722  0.22U_0603_25V7K  [C_0603]  147.81 153.12 270 top
PC723  0.1U_0402_10V7K  [C_0402]  138.23 149.5 180 top
PC725  0.1U_0402_16V7K  [C_0402]  139.63 149.58 270 top
PC726  0.1U_0603_25V7K  [C_0603]  147.81 150.71 270 top
PC727  0.01U_0402_25V7K  [C_0402]  136.38 150.46 270 top
PC901  22U_0603_6.3V6M  [C_0603]  137.74 120.94 180 top
PC902  22U_0603_6.3V6M  [C_0603]  80.7 23.39 270 bottom
PC903  22U_0603_6.3V6M  [C_0603]  137.74 119.57 180 top
PC904  22U_0603_6.3V6M  [C_0603]  79.43 23.39 270 bottom
PC905  22U_0603_6.3V6M  [C_0603]  126.49 119.72 0 top
PC906  22U_0603_6.3V6M  [C_0603]  78.16 23.39 270 bottom
PC907  22U_0603_6.3V6M  [C_0603]  126.49 118.45 0 top
PC908  22U_0603_6.3V6M  [C_0603]  76.89 23.39 270 bottom
PC909  220U_D2_2VY_R15M  [C_D2]  131.22 116.16 0 bottom
PC911  220U_D2_2VY_R15M  [C_D2]  134.65 120.99 0 bottom
PC913  22U_0603_6.3V6M  [C_0603]  119.06 120.8 90 top
PC914  22U_0603_6.3V6M  [C_0603]  117.79 120.8 90 top
PC915  22U_0603_6.3V6M  [C_0603]  116.52 120.8 90 top
PC916  22U_0603_6.3V6M  [C_0603]  120.33 120.8 90 top
PC917  220U_D2_2VY_R15M  [C_D2]  109.64 126.3 90 bottom
PC918  220U_D2_2VY_R15M  [C_D2]  114.46 126.27 90 bottom
PC919  220U_D2_2VY_R15M  [C_D2]  111.33 121.5 180 bottom
PC920  22U_0603_6.3V6M  [C_0603]  125.98 95.75 225 top
PC921  22U_0603_6.3V6M  [C_0603]  124.33 93.87 135 top
PC922  22U_0603_6.3V6M  [C_0603]  123.82 98.04 225 top
PC923  1U_0402_6.3V6K  [C_0402]  120.08 95.07 315 top
PC924  1U_0402_6.3V6K  [C_0402]  121.23 96.08 45 top
PC925  1U_0402_6.3V6K  [C_0402]  124.15 96.85 315 top
PC926  0.1U_0402_16V7K  [C_0402]  113.21 121.04 90 top
PC927  0.1U_0402_16V7K  [C_0402]  114.23 121.04 90 top
PC928  0.1U_0402_16V7K  [C_0402]  115.25 121.04 90 top
PC929  22U_0603_6.3V6M  [C_0603]  116.99 87.14 45 top
PC930  10U_0603_6.3V6M  [C_0603]  122.33 94.01 315 top
PC931  22U_0603_6.3V6M  [C_0603]  119.55 91.17 315 top
PC932  22U_0603_6.3V6M  [C_0603]  120.62 92.32 315 top
PC933  2.2U_0402_6.3V6M  [C_0402]  118.3 90.06 315 top
PC934  2.2U_0402_6.3V6M  [C_0402]  122.81 90.29 45 top
PD1  -  [TVNST52302AB0_SOT523-3]  158.43 174.01 0 top
PD2  -  [TVNST52302AB0_SOT523-3]  156.39 172.36 180 top
PH1  100K 1% 0402 B25/50 4250K  [R_0402]  135.6 93.99 180 top
PH500  10K 1% 0402 B25/50 3370K  [R_0402]  117.49 130.09 270 bottom
PH501  470K +-5% 0402 B25/50 4700K  [R_0402]  118.24 134.96 180 top
PH502  470K +-5% 0402 B25/50 4700K  [R_0402]  132.77 133.48 90 top
PH503  10K 1% 0402 B25/50 3370K  [R_0402]  135.47 129.32 90 bottom
PJP1  PAD-OPEN 1x3m  [JUMP_43X118]  103.69 157.63 0 top
PJP4  -  [JUMP_43X79]  165.03 171.92 90 top
PJP100  -  [JUMP_43X118]  52.72 23.96 0 bottom
PJP101  -  [JUMP_43X118]  37.52 25.27 270 top
PJP102  -  [JUMP_43X118]  48.88 45.88 270 top
PJP200  -  [JUMP_43X118]  53.9 42.12 270 top
PJP201  -  [JUMP_43X118]  70.75 23.71 0 bottom
PJP202  -  [JUMP_43X39]  61.83 53.81 0 top
PJP300  -  [JUMP_43X39]  156.44 96.1 0 bottom
PJP301  -  [JUMP_43X39]  161.09 90.33 270 bottom
PJP302  -  [JUMP_43X39]  151.06 113.16 90 bottom
PJP303  -  [JUMP_43X79]  152.58 109.6 270 bottom
PJP400  -  [JUMP_43X39]  40.87 24.21 0 top
PJP401  -  [JUMP_43X39]  49.51 16.85 0 top
PJP404  -  [JUMP_43X39]  151.27 88.39 0 bottom
PJP405  -  [JUMP_43X39]  152.24 85.58 180 bottom
PJP500  -  [JUMP_43X79]  113.22 144.18 180 bottom
PJP700  -  [JUMP_43X118]  155.18 162.9 180 bottom
PJPDC1  ACES_50458-00601-001  [ACES_50458-00601-001_6P-T]  102.9 161.77 180 top
PL1  FBMJ4516HS720NT_2P  [MURAT_BLM41PG600SN1L_2P]  92.95 158.16 0 top
PL2  FBMJ4516HS720NT_2P  [MURAT_BLM41PG600SN1L_2P-NPM]  102.21 158.03 0 top
PL3  BLM15AG102SN1D_2P  [MURAT_BLM15AG102SN1D_2P]  111.01 170.26 0 top
PL4  FBMJ4516HS720NT_2P  [MURAT_BLM41PG600SN1L_2P-NPM]  165.28 170.83 90 top
PL100  4.7UH_5.5A_20%_7X7X3_M  [L_7X7X3_M_2P]  36.86 34.54 180 bottom
PL101  4.7UH_5.5A_20%_7X7X3_M  [L_7X7X3_M_2P]  43.56 34.56 0 bottom
PL102  FBMJ4516HS720NT_2P  [MURAT_BLM41PG600SN1L_2P-NPM]  48.75 47.22 270 top
PL200  1UH_11A_20%_7X7X3_M  [L_7X7X3_M_2P]  58.1 33.89 90 bottom
PL300  1UH +-20% 2.3A 2.5X2X1.2 FERRITE  [TOKO_1239AS-H-1R0M-P2_2P]  163.74 95.08 180 bottom
PL301  1UH +-20% 2.3A 2.5X2X1.2 FERRIT  [TOKO_1239AS-H-1R0M-P2_2P]  157.44 113.62 180 bottom
PL400  1UH +-20% 2.3A 2.5X2X1.2 FERRITE  [TOKO_1239AS-H-1R0M-P2_2P]  47.94 21.15 270 top
PL500  0.22UH_24A_20%_7X7X4_MOLDING  [PANAS_ETQP4LR15AFM_4P]  122.23 134.2 270 bottom
PL501  0.22UH_24A_20%_7X7X4_MOLDING  [PANAS_ETQP4LR15AFM_4P]  130.74 134.58 270 bottom
PL502  HCB2012KF-121T50_0805  [TAI-T_HCB2012KF-121T50_2P]  113.44 141.33 180 bottom
PL700  10UH_3.5A_20%_7X7X3_M  [L_7X7X3_M_2P]  155.02 156.17 0 bottom
PL701  1UH_2.8A_30%_4X4X2_F  [L_4X4X2_F_2P-NPM]  156.02 162.9 180 bottom
PQ1  FDV301N_G 1N SOT23-3  [FDV301N_NL_SOT23-3]  111.92 168.42 180 top
PQ2  MMST3904-7-F_SOT323~D  [RHU002N06_SOT323-3]  108.64 166.16 0 top
PQ3  L2N7002DW1T1G_SC88-6  [2N7002DW-T-R7_SOT363-6]  129.12 161.52 270 top
PQ4  L2N7002DW1T1G_SC88-6  [2N7002DW-T-R7_SOT363-6]  117.18 168.37 270 top
PQ10  DMN66D0LDW-7 2N SOT363-6  [2N7002DW-T-R7_SOT363-6]  171.37 143.72 180 bottom
PQ101  -  [MDV1528URH_PDFN33-8-5]  30.96 41.28 0 top
PQ102  -  [MDV1528URH_PDFN33-8-5]  43.4 41.28 0 top
PQ103  -  [MDV1527URH_POWERDFN33-8-5]  33.54 37.84 90 top
PQ104  -  [MDV1527URH_POWERDFN33-8-5]  42.96 39.55 270 top
PQ201  -  [MDV1528URH_PDFN33-8-5]  62.11 39.75 90 top
PQ203  -  [MDV1527URH_POWERDFN33-8-5]  59.16 37.63 270 top
PQ501  AON7934_DFN3X3A-8-10  [AON7934_DFN3X3A8-10]  119.66 137.89 270 top
PQ503  AON7934_DFN3X3A-8-10  [AON7934_DFN3X3A8-10]  131.83 135.82 90 top
PQ701  MDV1525URH 1N PDFN33-8  [SIS412DN-T1-GE3_POWERPAK8-5]  158.34 158.35 90 top
PQ703  MDV1525URH 1N PDFN33-8  [SIS412DN-T1-GE3_POWERPAK8-5]  155.47 156.52 270 top
PQ704  -  [AO4407AL_SO8]  99.18 152.32 90 top
PQ705  SI4483ADY_SO8  [SI4459ADY-T1-GE3_SO8]  101.69 154 270 top
PQ706  -  [AO4407AL_SO8]  158.64 160.74 90 bottom
PQ707  LMUN5113T1G PNP SOT323-3  [DTA144EUA_SC70-3]  98.98 149.02 0 top
PQ708  LMUN5236T1G NPN SOT323-3  [DTC115EUA_SC70-3]  135.82 167.76 180 top
PQ709  DMN66D0LDW-7 2N SOT363-6  [2N7002DW-T-R7_SOT363-6]  133.68 168.08 180 top
PQ710  DMN66D0LDW-7 2N SOT363-6  [2N7002DW-T-R7_SOT363-6]  130.84 163.26 90 top
PQ711  LMUN5236T1G NPN SOT323-3  [DTC115EUA_SC70-3]  159.73 167.72 90 top
PQ712  LMUN5236T1G NPN SOT323-3  [DTC115EUA_SC70-3]  134.51 170.01 270 top
PQ713  DMN66D0LDW-7 2N SOT363-6  [2N7002DW-T-R7_SOT363-6]  133.18 164.56 270 top
PR1  33_0402_5%  [R_0402]  114.48 165.74 90 top
PR2  100K_0402_1%  [R_0402]  109.2 170.26 0 top
PR3  10K_0402_1%  [R_0402]  109.35 164.93 180 top
PR4  2.2K_0402_5%  [R_0402]  114.48 167.77 90 top
PR5  15K_0402_1%  [R_0402]  108.44 169.25 0 top
PR6  100_0402_5%  [R_0402]  156.9 176.31 270 top
PR7  10K_0402_1%  [R_0402]  155.89 175.34 180 top
PR8  100_0402_5%  [R_0402]  158.93 176.31 270 top
PR9  100_0402_5%  [R_0402]  158.01 176.3 270 top
PR10  16.9K_0402_1%  [R_0402]  147.2 138.01 180 top
PR11  30.1K_0402_1%  [R_0402]  147.2 135.97 180 top
PR12  3.3K_1206_5%~D  [R_1206]  131.31 158.33 180 top
PR13  0_0402_5%  [R0402_0OHM]  146.28 136.99 0 top
PR14  1M_0402_1%  [R_0402]  133.53 160.82 270 top
PR15  0_0402_5%  [R0402_0OHM]  146.28 132.67 0 top
PR16  200K_0402_1%  [R_0402]  126.47 162.64 0 top
PR17  160K_0402_1%  [R_0402]  115.5 165.74 90 top
PR18  10K_0402_1%  [R_0402]  146.28 134.7 0 top
PR19  1M_0402_1%  [R_0402]  132.52 159.9 90 top
PR20  787K_0402_1%  [R_0402]  146.28 133.69 0 top
PR21  10K_0402_1%  [R_0402]  127.39 161.63 180 top
PR22  60.4K_0402_1%  [R_0402]  170.25 141.05 90 bottom
PR23  115K_0402_1%  [R_0402]  172.07 141.05 90 bottom
PR26  100K_0402_1%  [R_0402]  120.63 166.71 0 top
PR34  80.6K_0402_1%  [R_0402]  165.97 131.02 0 top
PR35  10K_0402_1%  [R_0402]  163.96 131.91 180 top
PR36  0_0402_5%  [R_0402]  164.06 130.64 0 top
PR100  6.49K_0402_1%  [R_0402]  37.17 51.13 270 top
PR101  15K_0402_1%  [R_0402]  39.45 50.21 90 top
PR102  10K_0402_1%  [R_0402]  36.21 51.13 270 bottom
PR103  10K_0402_1%  [R_0402]  40.4 50.21 90 bottom
PR104  133K_0402_1%  [R_0402]  36.23 51.13 270 top
PR105  180K_0402_1%  [R_0402]  40.39 50.21 90 top
PR106  10K_0402_5%  [R_0402]  34.4 48.89 0 top
PR107  0_0603_5%  [R0603_0OHM]  33.06 46.07 0 top
PR108  0_0603_5%  [R0603_0OHM]  42.08 46.07 0 top
PR109  4.7_1206_5%  [R_1206]  30.85 35.64 0 top
PR110  4.7_1206_5%  [R_1206]  45.71 35.64 180 top
PR111  2.2_1206_1%  [R_1206]  36.12 40.47 90 bottom
PR112  0_0402_5%  [R0402_0OHM]  42.09 50.17 90 top
PR113  0_0402_5%  [R0402_0OHM]  44.76 50.13 90 bottom
PR114  0_0402_5%  [R0402_0OHM]  43.11 53.12 270 top
PR115  2.2K_0402_1%  [R_0402]  42.09 53.12 270 top
PR116  402K_0402_1%  [R_0402]  44.13 52.2 90 top
PR117  0_0402_5%  [R_0402]  42.06 48.52 0 top
PR200  0_0603_5%  [R0603_0OHM]  61.79 47.87 90 top
PR201  6.2K_0402_1%  [R_0402]  58.06 45.2 90 top
PR202  4.7_1206_5%  [R_1206]  61.4 33.74 180 top
PR203  5.1_0603_5%  [R_0603]  54.55 44.95 90 top
PR204  54.9K_0402_1%  [R_0402]  55.18 53.13 0 top
PR205  887K_0402_1%  [R_0402]  53.66 48.26 0 top
PR206  68.1K_0402_1%  [R_0402]  54.03 54.14 270 top
PR207  0_0402_5%  [R0402_0OHM]  53.61 50.16 0 top
PR208  0_0402_5%  [R0402_0OHM]  53.63 52.04 0 top
PR209  2.2_0603_5%  [R_0603]  56.33 48.09 0 bottom
PR210  10K_0402_5%  [R_0402]  53.65 47.38 0 top
PR300  2.55K_0402_1%  [R_0402]  161.22 101.63 270 bottom
PR301  4.7_0603_5%  [R_0603]  163 97.18 90 bottom
PR302  15K_0402_1%  [R_0402]  159.19 101.63 270 bottom
PR303  1M_0402_1%  [R_0402]  162.24 100.72 90 bottom
PR304  20K_0402_1%  [R_0402]  158.17 100.72 90 bottom
PR305  1M_0402_1%  [R_0402]  154.62 119.01 90 bottom
PR306  4.7_0603_5%  [R_0603]  156.65 115.72 90 bottom
PR307  13.7K_0402_1%  [R_0402]  151.57 119.92 270 bottom
PR308  10K_0402_5%  [R_0402]  153.6 119.92 270 bottom
PR309  20K_0402_1%  [R_0402]  150.55 119.01 90 bottom
PR400  20K_0402_1%  [R_0402]  43.87 18.93 90 top
PR401  4.7_0603_5%  [R_0603]  47.17 23.01 90 top
PR402  40.2K_0402_1%  [R_0402]  41.13 20.15 0 top
PR403  1M_0402_1%  [R_0402]  44.89 19.85 270 top
PR404  20K_0402_1%  [R_0402]  42.04 19.13 180 top
PR409  51.1K_0402_1%  [R_0402]  158.27 94.32 270 bottom
PR410  17.8K_0402_1%  [R_0402]  158.49 84.11 90 bottom
PR411  100K_0402_1%  [R_0402]  156.24 93.4 90 bottom
PR412  20K_0402_1%  [R_0402]  156.71 85.02 270 bottom
PR500  2.61K_0402_1%  [R_0402]  116.87 150.81 90 top
